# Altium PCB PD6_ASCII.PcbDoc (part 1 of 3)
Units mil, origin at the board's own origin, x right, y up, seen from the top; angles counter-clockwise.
Board outline 8543.31 x 5314.96 mil, 4 copper layers (Top Layer, VBAT Plane, GND Plane, Bottom Layer), stack 62.8 mil thick; 258 components, 142 nets, 690 pads, 87 vias.
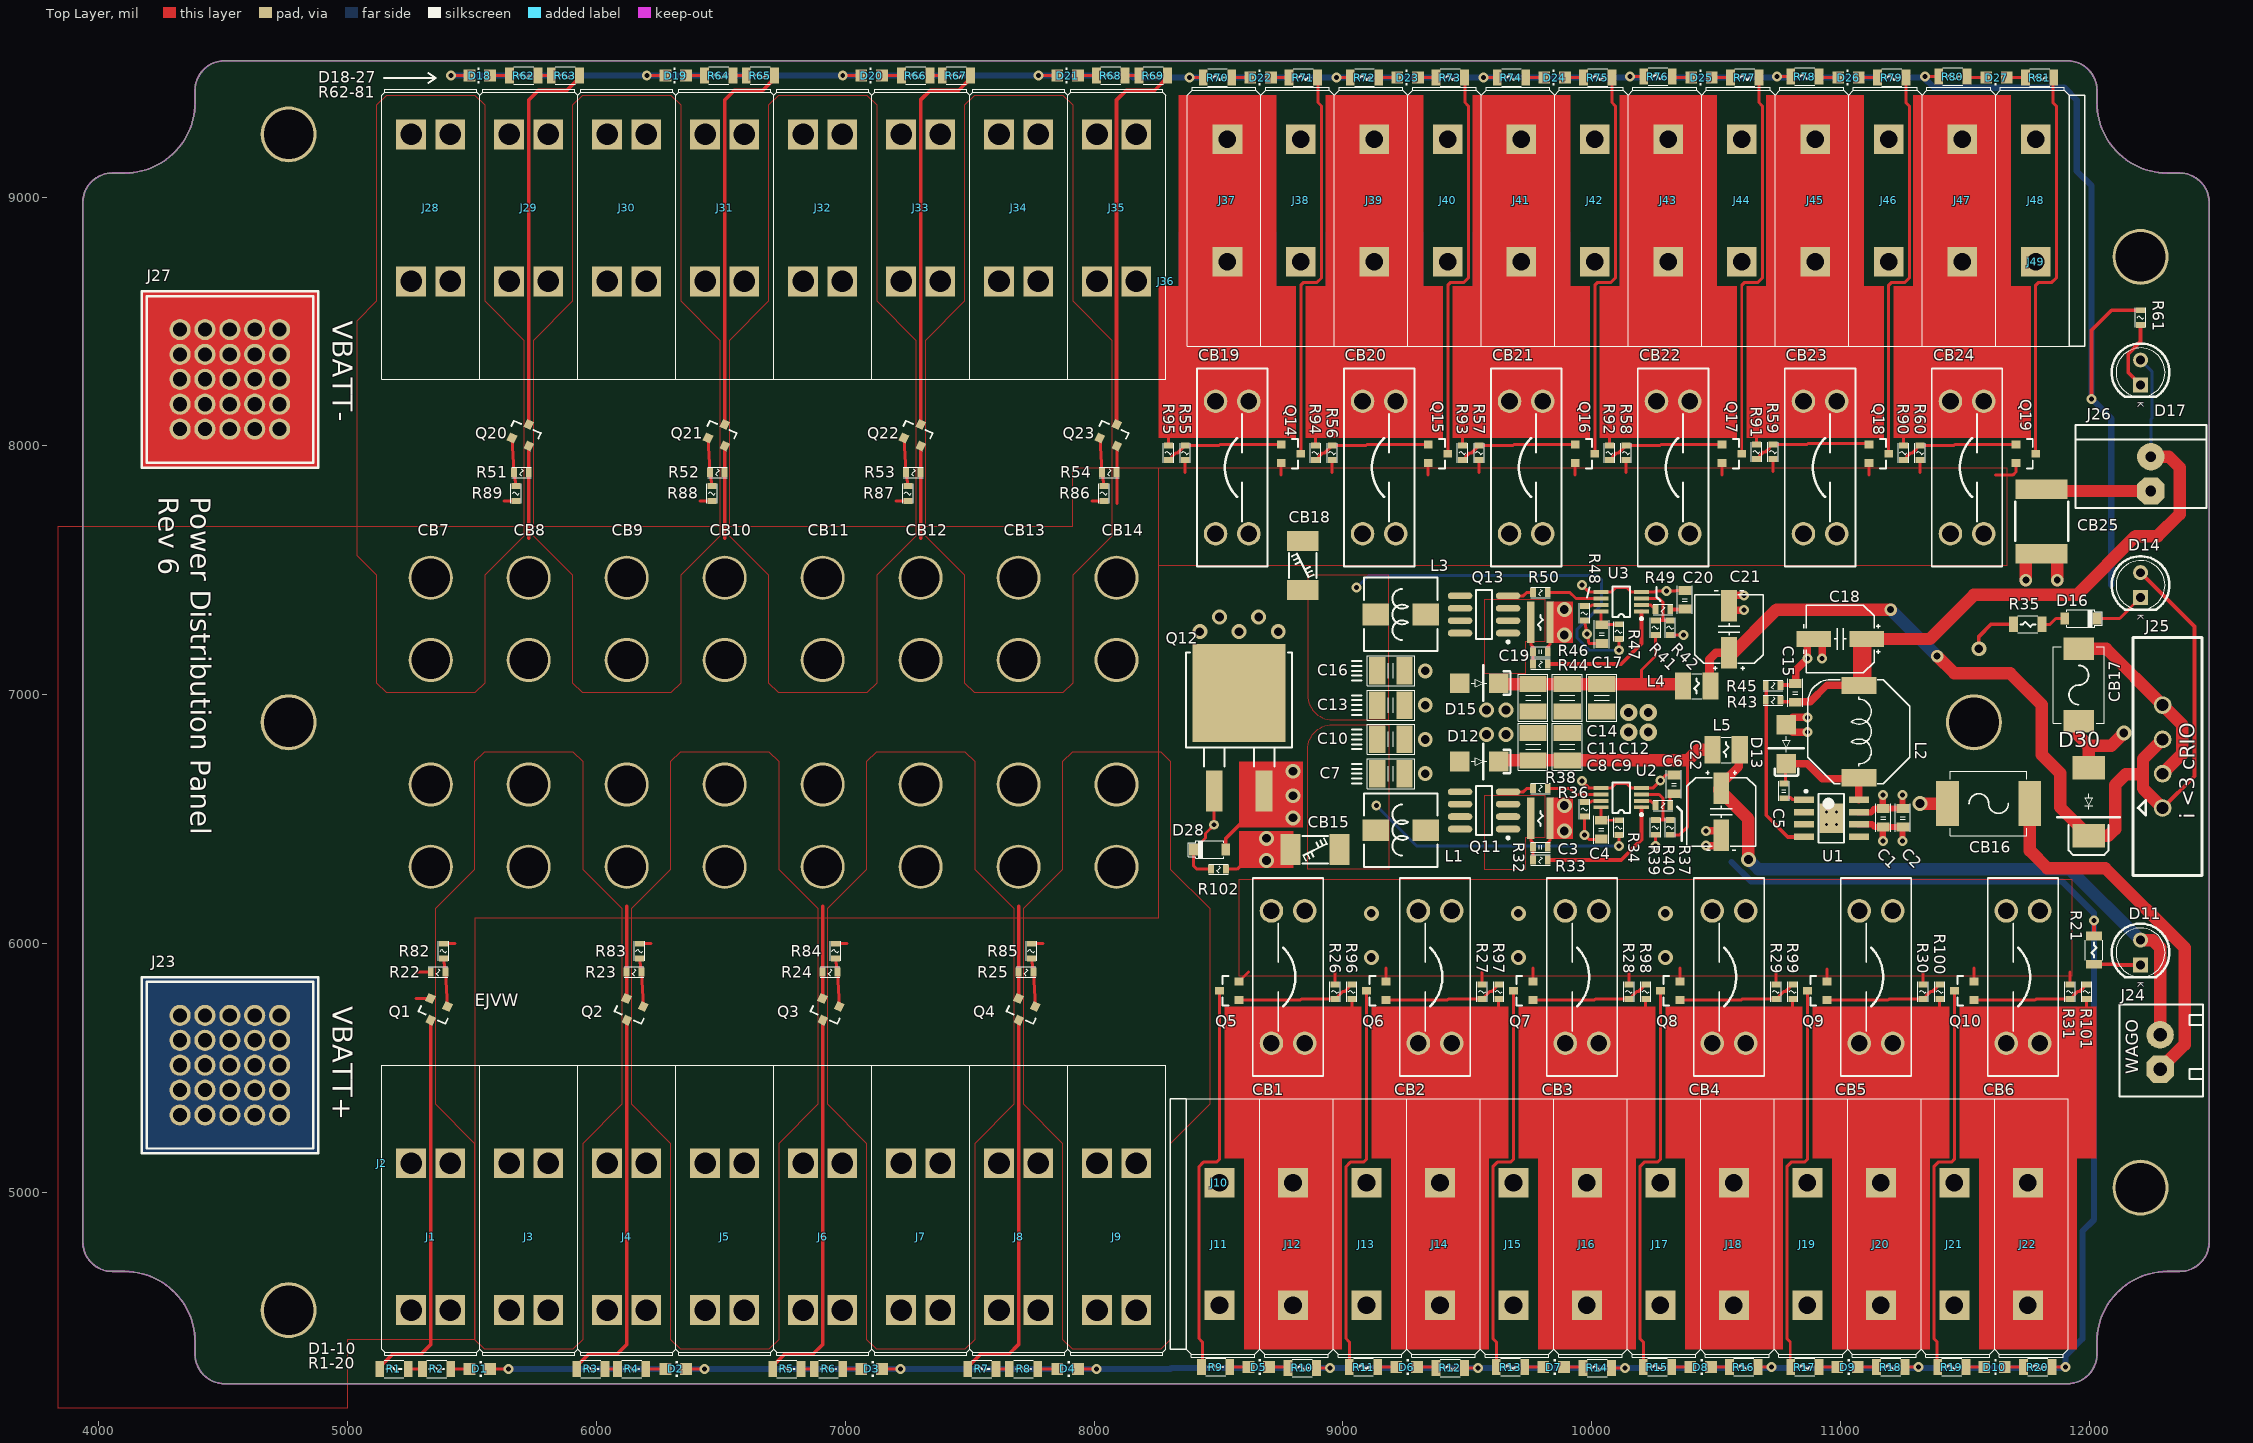
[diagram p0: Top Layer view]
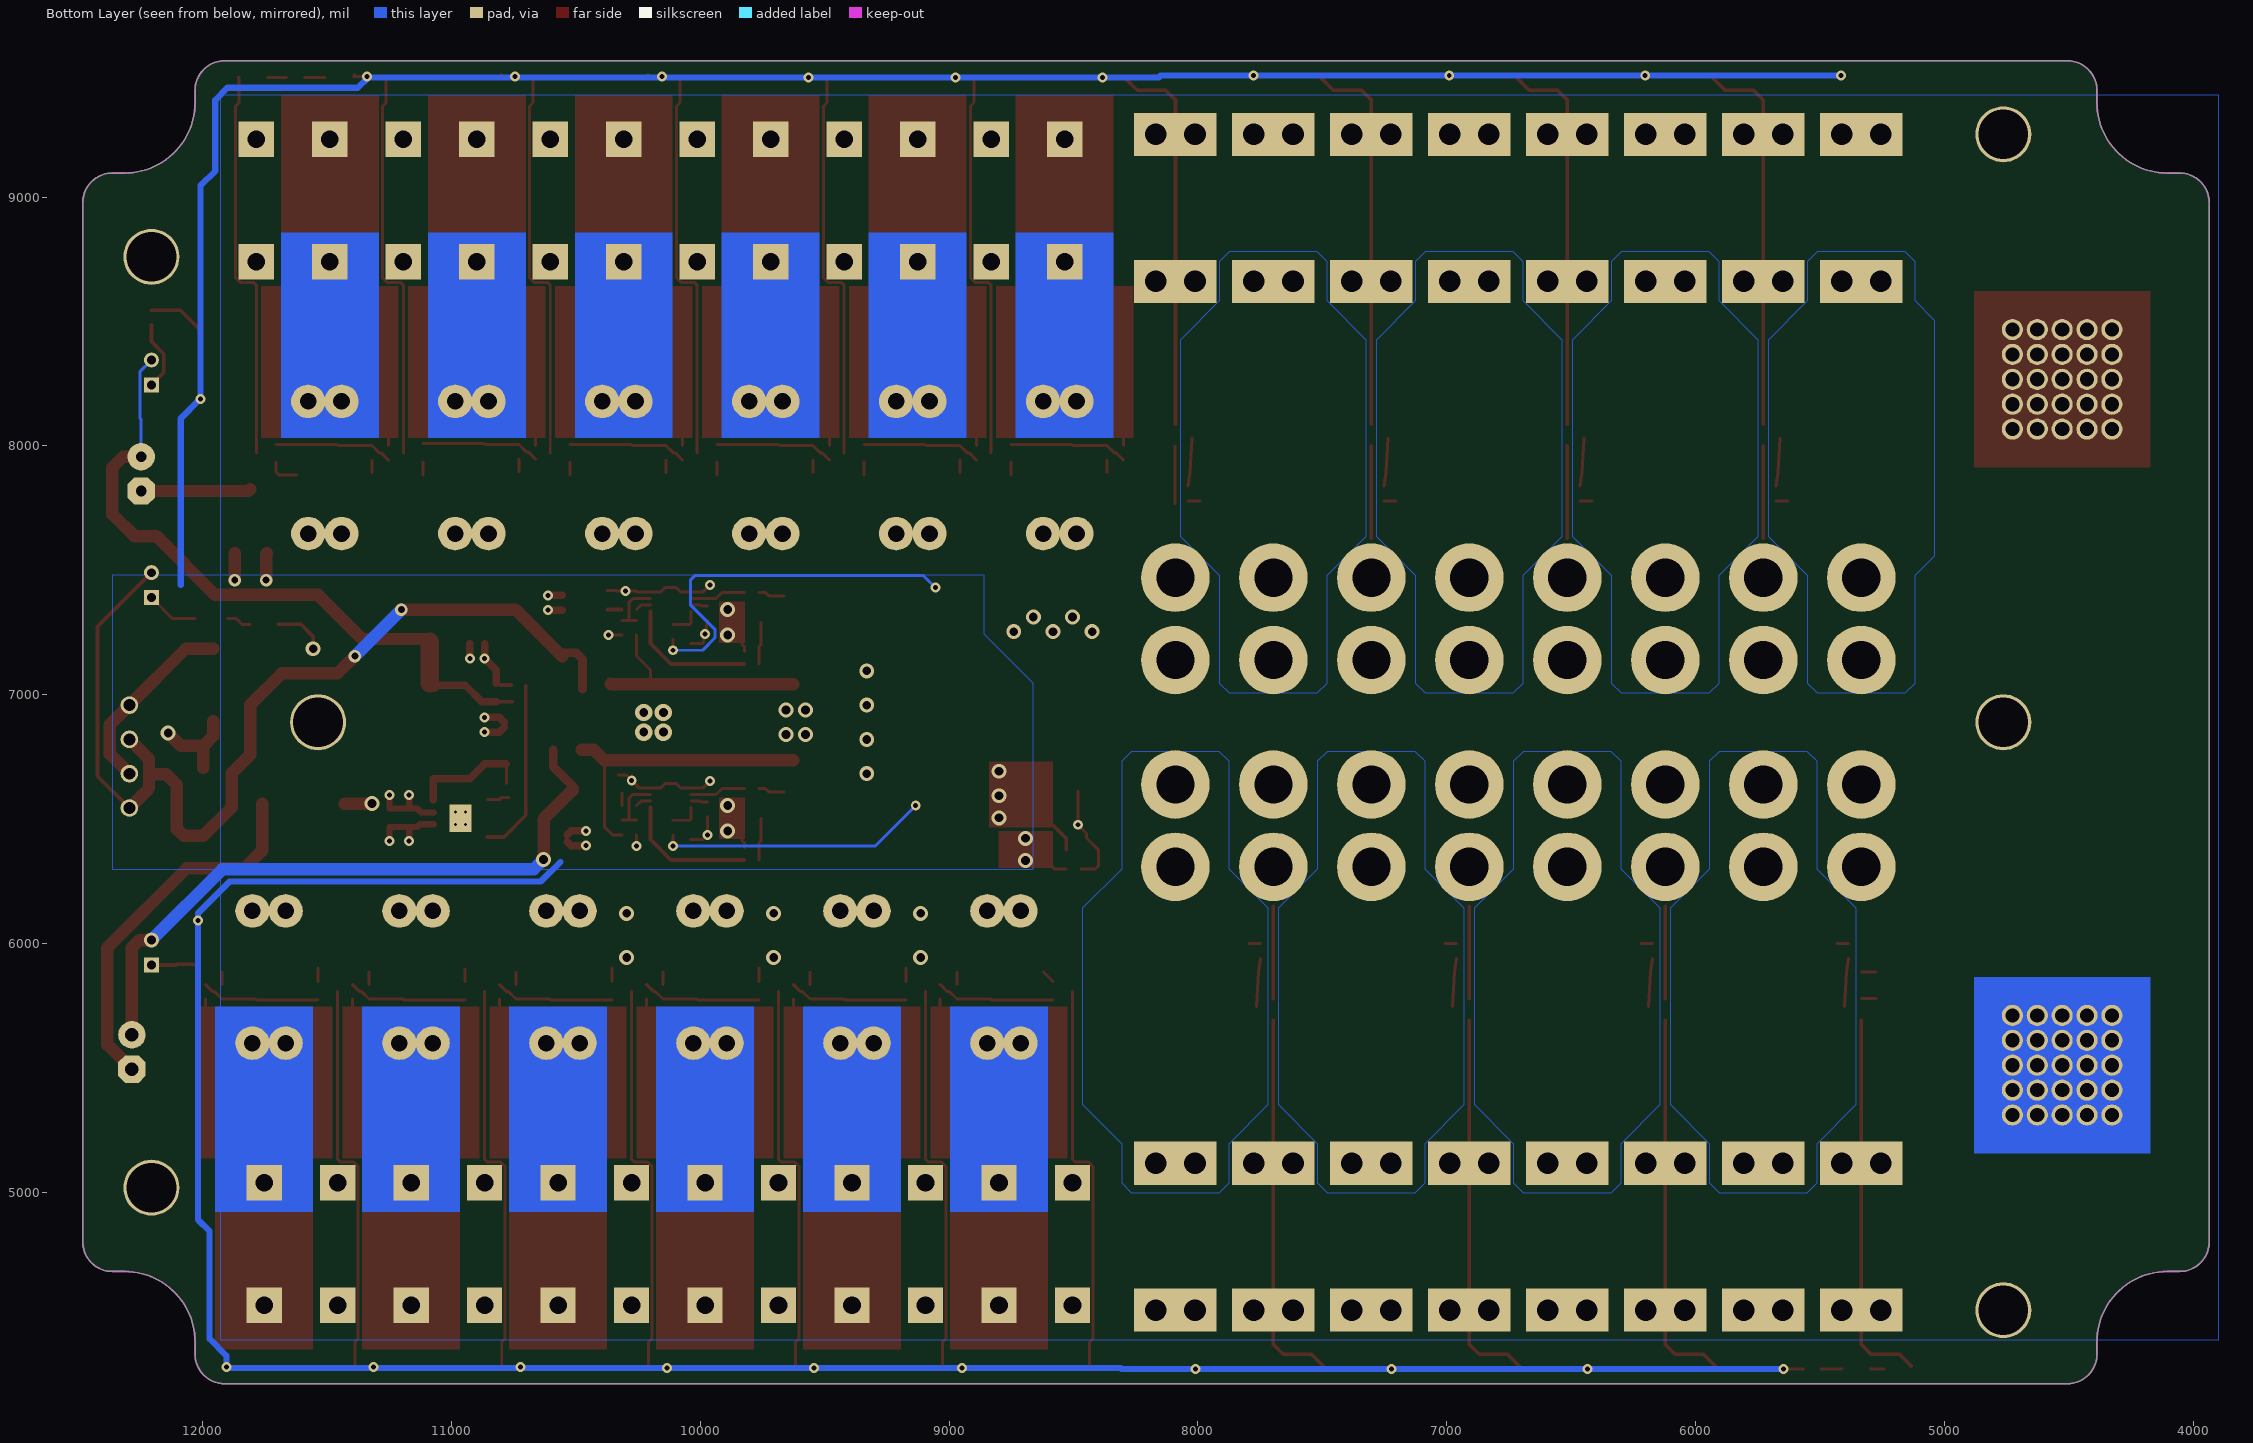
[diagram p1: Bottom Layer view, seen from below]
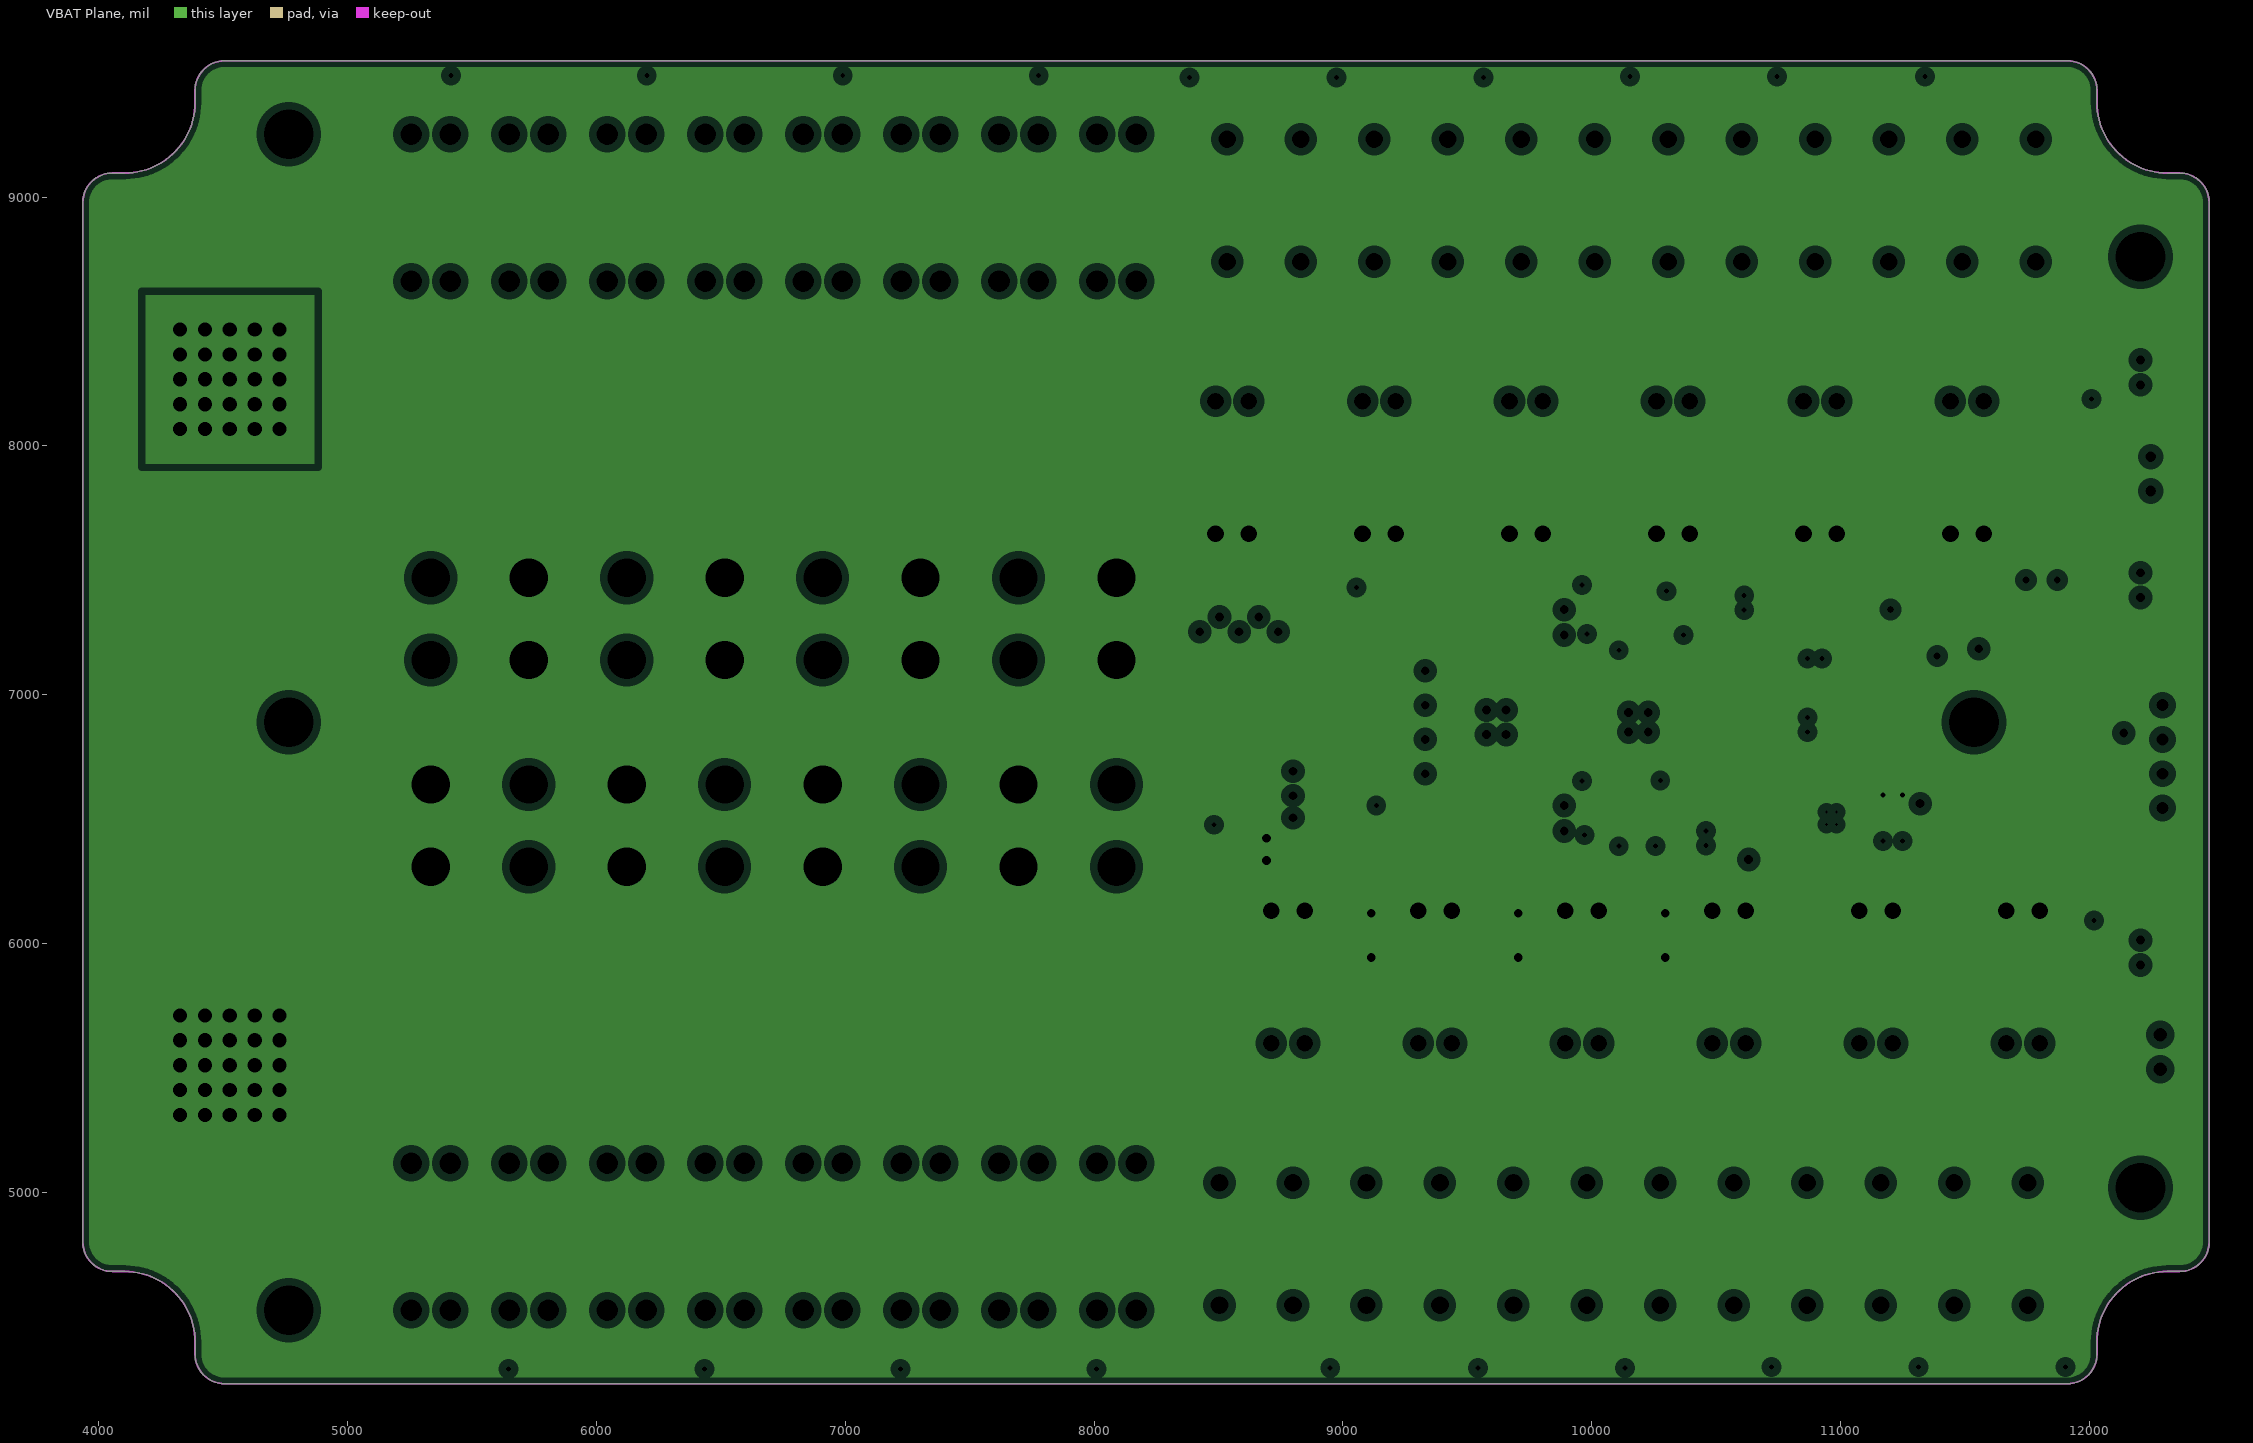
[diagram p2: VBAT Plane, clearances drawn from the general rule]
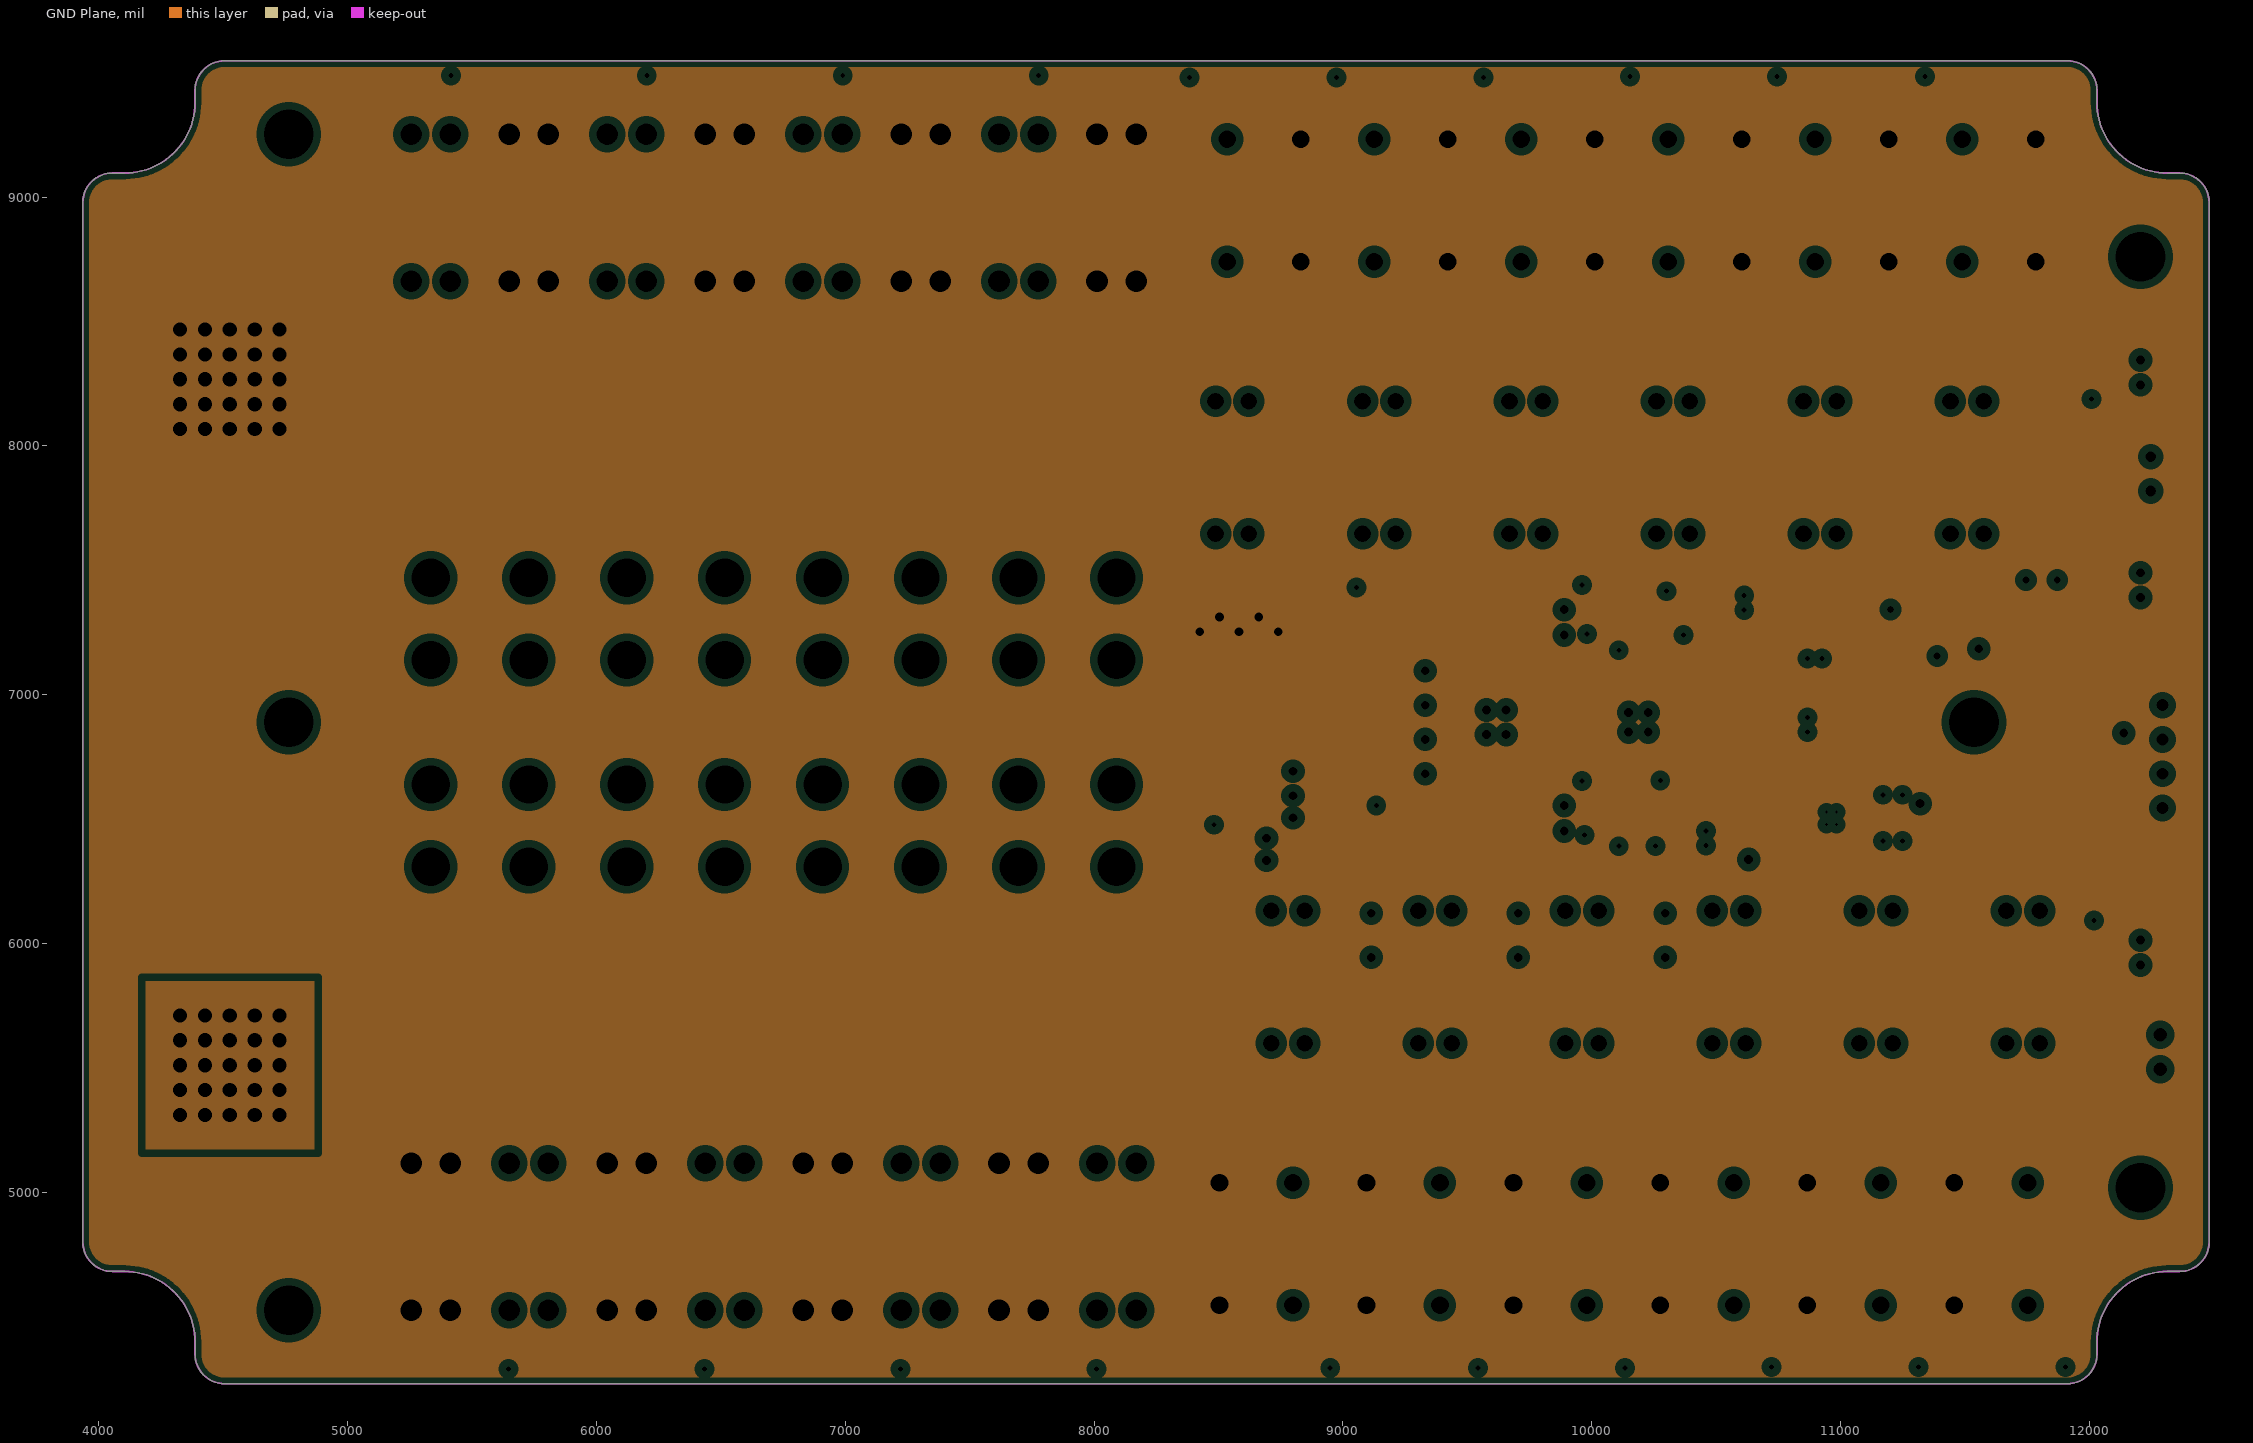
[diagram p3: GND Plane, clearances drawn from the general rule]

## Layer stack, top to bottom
Top Layer: signal copper 2.4
Dielectric: prepreg 10, FR-4, Dk 4.8
VBAT Plane: plane copper 5, net (Multiple Nets)
Dielectric: core 28, FR-4, Dk 4.8
GND Plane: plane copper 5, net (Multiple Nets)
Dielectric: prepreg 10, FR-4, Dk 4.8
Bottom Layer: signal copper 2.4

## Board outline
4055.12,4683.07 4104.33,4683.07 cw(c4104.33,4399.61) 4387.8,4399.61 4387.8,4350.39 ccw(c4505.91,4350.39) 4505.91,4232.28 11911.42,4232.28 ccw(c11911.42,4350.39) 12029.53,4350.39 12029.53,4399.61 cw(c12312.99,4399.61) 12312.99,4683.07 12362.2,4683.07 ccw(c12362.2,4801.18) 12480.31,4801.18 12480.31,8978.35 ccw(c12362.2,8978.35) 12362.2,9096.46 12312.99,9096.46 cw(c12312.99,9379.92) 12029.53,9379.92 12029.53,9429.13 ccw(c11911.42,9429.13) 11911.42,9547.24 4505.91,9547.24 ccw(c4505.91,9429.13) 4387.8,9429.13 4387.8,9379.92 cw(c4104.33,9379.92) 4104.33,9096.46 4055.12,9096.46 ccw(c4055.12,8978.35) 3937.01,8978.35 3937.01,4801.18 ccw(c4055.12,4801.18)

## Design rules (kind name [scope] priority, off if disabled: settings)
Clearance Clearance_Breakers [All] p0 off: scope1count=1 scope1_0_kind=Board scope1_0_value=Board scope2count=1 scope2_0_kind=Board scope2_0_value=Board commentlength=107 gap=18 // Protel DXP Scope 1 Expression Was: (HasFootprint('KEYSTONE 3555-2') OR HasFootprint('KEYSTONE 3557-2'))
Clearance Clearance_PolyPoly [All] p0 off: scope1count=1 scope1_0_kind=Board scope1_0_value=Board scope2count=1 scope2_0_kind=Board scope2_0_value=Board commentlength=69 gap=10 // Protel DXP Scope 2 Expression Was: (InPolygon or IsPad or IsFill)
Clearance CLR_Poly [All] p0 off: scope1count=1 scope1_0_kind=Board scope1_0_value=Board scope2count=1 scope2_0_kind=Board scope2_0_value=Board commentlength=50 gap=12 // Protel DXP Scope 1 Expression Was: (InPolygon)
Clearance CLR_Board_Edge [All] p0 off: scope1count=1 scope1_0_kind=Board scope1_0_value=Board scope2count=1 scope2_0_kind=Layer scope2_0_value=TOP commentlength=50 gap=20 // Protel DXP Scope 1 Expression Was: (InPolygon)
Clearance [All] p0: scope1count=1 scope1_0_kind=Board scope1_0_value=Board scope2count=1 scope2_0_kind=Board scope2_0_value=Board commentlength=0 gap=9.02
Clearance "CLR Inner Planes" [All] p0 off: scope1count=1 scope1_0_kind=Board scope1_0_value=Board scope2count=1 scope2_0_kind=Board scope2_0_value=Board commentlength=84 gap=30 // Protel DXP Scope 1 Expression Was: OnLayer('GND Plane') or OnLayer('VBAT Plane')
Clearance "CLR Inner Planes" [OnLayer('GND Plane') or OnLayer('VBAT Plane')] p1: gap=30
Clearance Clearance_Breakers [(HasFootprint('KEYSTONE 3555-2') OR HasFootprint('KEYSTONE 3557-2'))] p2: gap=18
Clearance CLR_Board_Edge [(InPolygon) vs OnLayer('Keep-Out Layer')] p3: gap=20
Clearance Clearance_PolyPoly [(InPolygon) vs (InPolygon or IsPad or IsFill)] p4: gap=10
Clearance CLR_Poly [(InPolygon)] p5: gap=12
Clearance [All] p6: gap=9.02
ComponentClearance "CC Wago236" [All] p0 off: scope1count=1 scope1_0_kind=Board scope1_0_value=Board scope2count=1 scope2_0_kind=Board scope2_0_value=Board commentlength=101 gap=-39.37 collisioncheckmode=3 // Protel DXP Scope 1 Expression Was: (HasFootprint('WAGO 236-74X') OR HasFootprint('WAGO 236-75X'))
ComponentClearance "ComponentClearance_WAGO Small" [All] p0 off: scope1count=1 scope1_0_kind=Board scope1_0_value=Board scope2count=1 scope2_0_kind=Board scope2_0_value=Board commentlength=137 gap=-3937.01 collisioncheckmode=3 // Protel DXP Scope 2 Expression Was: (HasFootprint('WAGO 745-83X') OR HasFootprint('WAGO 745-83X Red') OR HasFootprint('WAGO 745-300'))
ComponentClearance ComponentClearance_WAGOs [All] p0 off: scope1count=1 scope1_0_kind=Board scope1_0_value=Board scope2count=1 scope2_0_kind=Board scope2_0_value=Board commentlength=137 gap=-7874.02 collisioncheckmode=3 // Protel DXP Scope 2 Expression Was: (HasFootprint('WAGO 745-85X') OR HasFootprint('WAGO 745-85X Red') OR HasFootprint('WAGO 745-500'))
ComponentClearance [All] p0 off: scope1count=1 scope1_0_kind=Board scope1_0_value=Board scope2count=1 scope2_0_kind=Board scope2_0_value=Board commentlength=0 gap=10 collisioncheckmode=3
ComponentClearance "CC Wago236" [(HasFootprint('WAGO 236-74X') OR HasFootprint('WAGO 236-75X'))] p1 off: gap=-39.37 collisioncheckmode=3 verticalgap=0 showdistances=FALSE
ComponentClearance "ComponentClearance_WAGO Small" [(HasFootprint('WAGO 745-83X') OR HasFootprint('WAGO 745-83X Red') OR HasFootprint('WAGO 745-300')) vs (HasFootprint('WAGO 745-83X') OR HasFootprint('WAGO 745-83X Red') OR HasFootprint('WAGO 745-300'))] p2 off: gap=-3937.01 collisioncheckmode=3 verticalgap=0 showdistances=FALSE
ComponentClearance ComponentClearance_WAGOs [(HasFootprint('WAGO 745-85X') OR HasFootprint('WAGO 745-85X Red') OR HasFootprint('WAGO 745-500')) vs (HasFootprint('WAGO 745-85X') OR HasFootprint('WAGO 745-85X Red') OR HasFootprint('WAGO 745-500'))] p3 off: gap=-7874.02 collisioncheckmode=3 verticalgap=0 showdistances=FALSE
ComponentClearance [All] p4 off: gap=10 collisioncheckmode=3 verticalgap=10 showdistances=FALSE
DiffPairsRouting [All] p0: scope1count=1 scope1_0_kind=Board scope1_0_value=Board scope2count=1 scope2_0_kind=Board scope2_0_value=Board commentlength=0
FanoutControl Fanout_Default [All] p0: scope1count=1 scope1_0_kind=Board scope1_0_value=Board scope2count=1 scope2_0_kind=Board scope2_0_value=Board commentlength=30 // Fanout_Default (Default Rule)
FanoutControl Fanout_Small [All] p0 off: scope1count=1 scope1_0_kind=Board scope1_0_value=Board scope2count=1 scope2_0_kind=Board scope2_0_value=Board commentlength=84 // Protel DXP Scope 1 Expression Was: (CompPinCount < 5)   Fanout_Small (Default Rule)
FanoutControl Fanout_SOIC [All] p0 off: scope1count=1 scope1_0_kind=Board scope1_0_value=Board scope2count=1 scope2_0_kind=Board scope2_0_value=Board commentlength=71 // Protel DXP Scope 1 Expression Was: IsSOIC   Fanout_SOIC (Default Rule)
FanoutControl Fanout_LCC [All] p0 off: scope1count=1 scope1_0_kind=Board scope1_0_value=Board scope2count=1 scope2_0_kind=Board scope2_0_value=Board commentlength=69 // Protel DXP Scope 1 Expression Was: IsLCC   Fanout_LCC (Default Rule)
FanoutControl Fanout_BGA [All] p0 off: scope1count=1 scope1_0_kind=Board scope1_0_value=Board scope2count=1 scope2_0_kind=Board scope2_0_value=Board commentlength=69 // Protel DXP Scope 1 Expression Was: IsBGA   Fanout_BGA (Default Rule)
Height Height_Bottom [All] p0: scope1count=1 scope1_0_kind=Layer scope1_0_value=BOTTOM scope2count=1 scope2_0_kind=Board scope2_0_value=Board commentlength=0
Height [All] p0: scope1count=1 scope1_0_kind=Board scope1_0_value=Board scope2count=1 scope2_0_kind=Board scope2_0_value=Board commentlength=0
Height Height_Bottom [OnLayer('Bottom Layer')] p1: minheight=0 maxheight=137.8 prefheight=39.37
Height [All] p2: minheight=0 maxheight=2500 prefheight=500
HoleSize [All] p0: scope1count=1 scope1_0_kind=Board scope1_0_value=Board scope2count=1 scope2_0_kind=Board scope2_0_value=Board commentlength=0 absolutevalues=TRUE maxlimit=500 minlimit=10 maxpercent=80.000 minpercent=20.000
HoleSize [All] p1: absolutevalues=TRUE maxlimit=500 minlimit=10 maxpercent=80.000 minpercent=20.000
LayerPairs [All] p0: scope1count=1 scope1_0_kind=Board scope1_0_value=Board scope2count=1 scope2_0_kind=Board scope2_0_value=Board commentlength=0 enforce=TRUE
MinimumAnnularRing [All] p0: scope1count=1 scope1_0_kind=Board scope1_0_value=Board scope2count=1 scope2_0_kind=Board scope2_0_value=Board commentlength=0 minimumring=10
MinimumAnnularRing [All] p1: minimumring=10
PasteMaskExpansion [All] p0: scope1count=1 scope1_0_kind=Board scope1_0_value=Board scope2count=1 scope2_0_kind=Board scope2_0_value=Board commentlength=0 expansion=0
PlaneClearance [All] p0: scope1count=1 scope1_0_kind=Board scope1_0_value=Board scope2count=1 scope2_0_kind=Board scope2_0_value=Board commentlength=0 clearance=30
PlaneClearance [All] p1: clearance=30
PlaneConnect PC_Wurth [All] p0 off: scope1count=1 scope1_0_kind=Board scope1_0_value=Board scope2count=1 scope2_0_kind=Board scope2_0_value=Board commentlength=70 planeconnectstyle=Direct reliefexpansion=20 reliefentries=4 reliefconductorwidth=10 reliefairgap=10 // Protel DXP Scope 1 Expression Was: (HasFootprint('WURTH 7460719'))
PlaneConnect PC_Honkin [All] p0 off: scope1count=1 scope1_0_kind=Board scope1_0_value=Board scope2count=1 scope2_0_kind=Board scope2_0_value=Board commentlength=79 planeconnectstyle=Direct reliefexpansion=20 reliefentries=2 reliefconductorwidth=10 reliefairgap=10 // Protel DXP Scope 1 Expression Was: (InComponent('J1') OR InComponent('J2'))
PlaneConnect PC_Vias [All] p0 off: scope1count=1 scope1_0_kind=Board scope1_0_value=Board scope2count=1 scope2_0_kind=Board scope2_0_value=Board commentlength=44 planeconnectstyle=Direct reliefexpansion=20 reliefentries=4 reliefconductorwidth=10 reliefairgap=10 // Protel DXP Scope 1 Expression Was: IsVia
PlaneConnect [All] p0: scope1count=1 scope1_0_kind=Board scope1_0_value=Board scope2count=1 scope2_0_kind=Board scope2_0_value=Board commentlength=0 planeconnectstyle=Direct reliefexpansion=30 reliefentries=4 reliefconductorwidth=30 reliefairgap=20
PlaneConnect PC_Breakers [All] p0 off: scope1count=1 scope1_0_kind=Board scope1_0_value=Board scope2count=1 scope2_0_kind=Board scope2_0_value=Board commentlength=107 planeconnectstyle=Direct reliefexpansion=20 reliefentries=4 reliefconductorwidth=60 reliefairgap=20 // Protel DXP Scope 1 Expression Was: (HasFootprint('KEYSTONE 3555-2') OR HasFootprint('KEYSTONE 3557-2'))
PlaneConnect "PC Wagos" [All] p0 off: scope1count=1 scope1_0_kind=Board scope1_0_value=Board scope2count=1 scope2_0_kind=Board scope2_0_value=Board commentlength=101 planeconnectstyle=Direct reliefexpansion=20 reliefentries=4 reliefconductorwidth=40 reliefairgap=25 // Protel DXP Scope 1 Expression Was: (HasFootprint('WAGO 745-83X') OR HasFootprint('WAGO 745-85X'))
PlaneConnect PC_PowerSO8 [All] p0 off: scope1count=1 scope1_0_kind=Board scope1_0_value=Board scope2count=1 scope2_0_kind=Board scope2_0_value=Board commentlength=64 planeconnectstyle=Direct reliefexpansion=20 reliefentries=4 reliefconductorwidth=10 reliefairgap=10 // Protel DXP Scope 1 Expression Was: (HasFootprint('TPS543X'))
PlaneConnect PC_PowerSO8 [(HasFootprint('TPS543X'))] p1: planeconnectstyle=Direct reliefexpansion=20 reliefentries=4 reliefconductorwidth=10 reliefairgap=10
PlaneConnect PC_Wurth [(HasFootprint('WURTH 7460719'))] p2: planeconnectstyle=Direct reliefexpansion=20 reliefentries=4 reliefconductorwidth=10 reliefairgap=10
PlaneConnect "PC Wagos" [(HasFootprint('WAGO 745-83X') OR HasFootprint('WAGO 745-85X'))] p3: planeconnectstyle=Direct reliefexpansion=20 reliefentries=4 reliefconductorwidth=40 reliefairgap=25
PlaneConnect PC_Breakers [(HasFootprint('KEYSTONE 3555-2') OR HasFootprint('KEYSTONE 3557-2'))] p4: planeconnectstyle=Direct reliefexpansion=20 reliefentries=4 reliefconductorwidth=60 reliefairgap=20
PlaneConnect PC_Honkin [(InComponent('J1') OR InComponent('J2'))] p5: planeconnectstyle=Direct reliefexpansion=20 reliefentries=2 reliefconductorwidth=10 reliefairgap=10
PlaneConnect PC_Vias [IsVia] p6: planeconnectstyle=Direct reliefexpansion=20 reliefentries=4 reliefconductorwidth=10 reliefairgap=10
PlaneConnect [All] p7: planeconnectstyle=Direct reliefexpansion=30 reliefentries=4 reliefconductorwidth=30 reliefairgap=20
PolygonConnect PGC_Breakers [All] p0 off: scope1count=1 scope1_0_kind=Board scope1_0_value=Board scope2count=1 scope2_0_kind=Board scope2_0_value=Board commentlength=105 connectstyle=Direct reliefconductorwidth=50 reliefentries=4 polygonreliefangle="45 Angle" // Protel DXP Scope 1 Expression Was: HasFootprint('KEYSTONE 3555-2') OR HasFootprint('KEYSTONE 3557-2')
PolygonConnect PGC_Vias [All] p0 off: scope1count=1 scope1_0_kind=Board scope1_0_value=Board scope2count=1 scope2_0_kind=Board scope2_0_value=Board commentlength=46 connectstyle=Direct reliefconductorwidth=10 reliefentries=4 polygonreliefangle="90 Angle" // Protel DXP Scope 1 Expression Was: (IsVia)
PolygonConnect PGC_VBAT_HP [All] p0 off: scope1count=1 scope1_0_kind=Board scope1_0_value=Board scope2count=1 scope2_0_kind=Board scope2_0_value=Board commentlength=115 connectstyle=Direct reliefconductorwidth=10 reliefentries=4 polygonreliefangle="45 Angle" // Protel DXP Scope 2 Expression Was: IsNamedPolygon('Top Layer-VBAT HP') or IsNamedPolygon('Bottom Layer-GND HP')
PolygonConnect [All] p0: scope1count=1 scope1_0_kind=Board scope1_0_value=Board scope2count=1 scope2_0_kind=Board scope2_0_value=Board commentlength=0 connectstyle=Direct reliefconductorwidth=10 reliefentries=4 polygonreliefangle="90 Angle"
PolygonConnect "PGC Wago" [All] p0 off: scope1count=1 scope1_0_kind=Board scope1_0_value=Board scope2count=1 scope2_0_kind=Board scope2_0_value=Board commentlength=101 connectstyle=Direct reliefconductorwidth=45 reliefentries=4 polygonreliefangle="90 Angle" // Protel DXP Scope 1 Expression Was: (HasFootprint('WAGO 745-83X') OR HasFootprint('WAGO 745-85X'))
PolygonConnect "PGC Wago" [(HasFootprint('WAGO 745-83X') OR HasFootprint('WAGO 745-85X'))] p1: connectstyle=Direct reliefconductorwidth=45 reliefentries=4 polygonreliefangle="90 Angle"
PolygonConnect PGC_Breakers [HasFootprint('KEYSTONE 3555-2') OR HasFootprint('KEYSTONE 3557-2')] p2: connectstyle=Direct reliefconductorwidth=50 reliefentries=4 polygonreliefangle="45 Angle"
PolygonConnect PGC_Vias [(IsVia)] p3: connectstyle=Direct reliefconductorwidth=10 reliefentries=4 polygonreliefangle="90 Angle"
PolygonConnect PGC_VBAT_HP [All vs IsNamedPolygon('Top Layer-VBAT HP') or IsNamedPolygon('Bottom Layer-GND HP')] p4: connectstyle=Direct reliefconductorwidth=10 reliefentries=4 polygonreliefangle="45 Angle"
PolygonConnect [All] p5: connectstyle=Direct reliefconductorwidth=10 reliefentries=4 polygonreliefangle="90 Angle"
RoomDefinition U1000 [All] p0: scope1count=1 scope1_0_kind=ComponentClass scope1_0_value=U1000 scope2count=1 scope2_0_kind=Board scope2_0_value=Board commentlength=0 region_x1=88582677 region_y1=68897638 region_x2=108169291 region_y2=74803150 confinementstyle=ConfineIn
RoomDefinition "U_5V_3A Supply" [All] p0: scope1count=1 scope1_0_kind=ComponentClass scope1_0_value="U_5V_3A Supply" scope2count=1 scope2_0_kind=Board scope2_0_value=Board commentlength=0 region_x1=106692913 region_y1=63779528 region_x2=112992126 region_y2=73818898 confinementstyle=ConfineIn
RoomDefinition HPB2 [All] p0: scope1count=1 scope1_0_kind=ComponentClass scope1_0_value=HPB2 scope2count=1 scope2_0_kind=Board scope2_0_value=Board commentlength=0 region_x1=50393701 region_y1=61023622 region_x2=83858268 region_y2=96456693 confinementstyle=ConfineIn
RoomDefinition LPB1 [All] p0: scope1count=1 scope1_0_kind=ComponentClass scope1_0_value=LPB1 scope2count=1 scope2_0_kind=Board scope2_0_value=Board commentlength=0 region_x1=82874016 region_y1=41338583 region_x2=122244094 region_y2=68897638 confinementstyle=ConfineIn
RoomDefinition HPB1 [All] p0: scope1count=1 scope1_0_kind=ComponentClass scope1_0_value=HPB1 scope2count=1 scope2_0_kind=Board scope2_0_value=Board commentlength=0 region_x1=50393701 region_y1=41338583 region_x2=83858268 region_y2=76771654 confinementstyle=ConfineIn
RoomDefinition LPB2 [All] p0: scope1count=1 scope1_0_kind=ComponentClass scope1_0_value=LPB2 scope2count=1 scope2_0_kind=Board scope2_0_value=Board commentlength=0 region_x1=80629922 region_y1=68897638 region_x2=120000000 region_y2=96456693 confinementstyle=ConfineIn
RoomDefinition "U_12V_2A Supply" [All] p0: scope1count=1 scope1_0_kind=ComponentClass scope1_0_value="U_12V_2A Supply" scope2count=1 scope2_0_kind=Board scope2_0_value=Board commentlength=0 region_x1=88582677 region_y1=62992126 region_x2=108169291 region_y2=68897638 confinementstyle=ConfineIn
RoomDefinition "U_12V_2A Supply" [InComponentClass('U_12V_2A Supply')] p1: confinementstyle=ConfineIn formatcopy=TRUE lockcomponents=FALSE outline 8858.27,6299.21 10816.93,6299.21 10816.93,6889.76 8858.27,6889.76
RoomDefinition LPB2 [InComponentClass('LPB2')] p2: confinementstyle=ConfineIn formatcopy=TRUE lockcomponents=FALSE outline 8062.99,6889.76 12000,6889.76 12000,9645.67 8062.99,9645.67
RoomDefinition HPB1 [InComponentClass('HPB1')] p3: confinementstyle=ConfineIn formatcopy=TRUE lockcomponents=FALSE outline 8385.83,7677.17 5039.37,7677.17 5039.37,4133.86 8385.83,4133.86
RoomDefinition LPB1 [InComponentClass('LPB1')] p4: confinementstyle=ConfineIn formatcopy=TRUE lockcomponents=FALSE outline 12224.41,6889.76 8287.4,6889.76 8287.4,4133.86 12224.41,4133.86
RoomDefinition U1000 [InComponentClass('U1000')] p5: confinementstyle=ConfineIn formatcopy=TRUE lockcomponents=FALSE outline 8858.27,6889.76 10816.93,6889.76 10816.93,7480.31 8858.27,7480.31
RoomDefinition "U_5V_3A Supply" [InComponentClass('U_5V_3A Supply')] p6: confinementstyle=ConfineIn formatcopy=TRUE lockcomponents=FALSE outline 11299.21,6377.95 11299.21,7381.89 10669.29,7381.89 10669.29,6377.95
RoomDefinition HPB2 [InComponentClass('HPB2')] p7: confinementstyle=ConfineIn formatcopy=TRUE lockcomponents=FALSE outline 5039.37,6102.36 8385.83,6102.36 8385.83,9645.67 5039.37,9645.67
RoutingCorners [All] p0: scope1count=1 scope1_0_kind=Board scope1_0_value=Board scope2count=1 scope2_0_kind=Board scope2_0_value=Board commentlength=0 cornerstyle=45-Degree minsetback=100 maxsetback=100
RoutingLayers [All] p0: scope1count=1 scope1_0_kind=Board scope1_0_value=Board scope2count=1 scope2_0_kind=Board scope2_0_value=Board commentlength=0 top layer=Automatic bottom layer=Automatic
RoutingPriority [All] p0: scope1count=1 scope1_0_kind=Board scope1_0_value=Board scope2count=1 scope2_0_kind=Board scope2_0_value=Board commentlength=0
RoutingTopology [All] p0: scope1count=1 scope1_0_kind=Board scope1_0_value=Board scope2count=1 scope2_0_kind=Board scope2_0_value=Board commentlength=0 topology=Shortest
RoutingVias [All] p0: scope1count=1 scope1_0_kind=Board scope1_0_value=Board scope2count=1 scope2_0_kind=Board scope2_0_value=Board commentlength=0 holewidth=30 width=50 viastyle="Through Hole" minholewidth=10 minwidth=30 maxholewidth=225 maxwidth=250
RoutingVias [All] p1: holewidth=30 width=50 viastyle="Through Hole" minholewidth=10 minwidth=30 maxholewidth=225 maxwidth=250
ShortCircuit [All] p0: scope1count=1 scope1_0_kind=Board scope1_0_value=Board scope2count=1 scope2_0_kind=Board scope2_0_value=Board commentlength=0 allowed=FALSE
SolderMaskExpansion [All] p0: scope1count=1 scope1_0_kind=Board scope1_0_value=Board scope2count=1 scope2_0_kind=Board scope2_0_value=Board commentlength=0 expansion=4
SolderMaskExpansion [All] p1: expansion=4
TestPointUsage [All] p0: scope1count=1 scope1_0_kind=Board scope1_0_value=Board scope2count=1 scope2_0_kind=Board scope2_0_value=Board commentlength=0 valid=0 allowmultiple=FALSE
TestPointUsage [All] p1: valid=0 allowmultiple=FALSE
Testpoint [All] p0: scope1count=1 scope1_0_kind=Board scope1_0_value=Board scope2count=1 scope2_0_kind=Board scope2_0_value=Board commentlength=0 side=15 testpointundercomponent=TRUE minsize=40 maxsize=100 preferedsize=60 minholesize=0 maxholesize=40 preferedholesize=32 testpointgrid=1 style=1021 order=0-112345678
Testpoint [All] p1: side=15 testpointundercomponent=TRUE minsize=40 maxsize=100 preferedsize=60 minholesize=0 maxholesize=40 preferedholesize=32 testpointgrid=1 style=1021 order=0-112345678
UnRoutedNet [All] p0: scope1count=1 scope1_0_kind=Board scope1_0_value=Board scope2count=1 scope2_0_kind=Board scope2_0_value=Board commentlength=0
Width [All] p0: scope1count=1 scope1_0_kind=Board scope1_0_value=Board scope2count=1 scope2_0_kind=Board scope2_0_value=Board commentlength=0 maxlimit=500 minlimit=10 preferedwidth=12
Width Width_InnerPlanes [All] p0 off: scope1count=1 scope1_0_kind=Board scope1_0_value=Board scope2count=1 scope2_0_kind=Board scope2_0_value=Board commentlength=84 maxlimit=100 minlimit=25 preferedwidth=30 // Protel DXP Scope 1 Expression Was: OnLayer('GND Plane') or OnLayer('VBAT Plane')
Width Width_InnerPlanes [OnLayer('GND Plane') or OnLayer('VBAT Plane')] p1: maxlimit=100 minlimit=25 preferedwidth=30
Width [All] p2: maxlimit=500 minlimit=10 preferedwidth=12
14 further rules are at their usual default settings.

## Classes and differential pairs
component class "U_12V_2A Supply": C3 C4 C6 C7 C8 C9 C10 C22 D12 L1 L5 Q11 R32 R33 R34 R36 R37 R38 R39 R40 U2
component class "U_5V_3A Supply": C1 C2 C5 C15 C18 D13 L2 R43 R45 U1
component class PS1: CB15 CB16 CB17 CB18 CB25 D11 D14 D16 D17 D28 D30 J23 J24 J25 J26 J27 Q12 R21 R35 R61 R102
component class LPB2: CB19 CB20 CB21 CB22 CB23 CB24 D22 D23 D24 D25 D26 D27 J37 J38 J39 J40 J41 J42 J43 J44 J45 J46 J47 J48 J49 Q14 Q15 Q16 Q17 Q18 Q19 R55 R56 R57 R58 R59 R60 R70 R71 R72 R73 R74 R75 R76 R77 R78 R79 R80 R81 R90 R91 R92 R93 R94 R95
component class LPB1: CB1 CB2 CB3 CB4 CB5 CB6 D5 D6 D7 D8 D9 D10 J10 J11 J12 J13 J14 J15 J16 J17 J18 J19 J20 J21 J22 J50 Q5 Q6 Q7 Q8 Q9 Q10 R9 R10 R11 R12 R13 R14 R15 R16 R17 R18 R19 R20 R26 R27 R28 R29 R30 R31 R96 R97 R98 R99 R100 R101
component class HPB1: CB8 CB10 CB12 CB14 D1 D2 D3 D4 J1 J2 J3 J4 J5 J6 J7 J8 J9 Q1 Q2 Q3 Q4 R1 R2 R3 R4 R5 R6 R7 R8 R22 R23 R24 R25 R82 R83 R84 R85
channel class "PD - Low Power Bank": LPB1 LPB2
channel class "PD - High Power Bank": HPB1 HPB2
component class HPB2: CB7 CB9 CB11 CB13 D18 D19 D20 D21 J28 J29 J30 J31 J32 J33 J34 J35 J36 Q20 Q21 Q22 Q23 R51 R52 R53 R54 R62 R63 R64 R65 R66 R67 R68 R69 R86 R87 R88 R89
component class U1000: C11 C12 C13 C14 C16 C17 C19 C20 C21 D15 L3 L4 Q13 R41 R42 R44 R46 R47 R48 R49 R50 U3

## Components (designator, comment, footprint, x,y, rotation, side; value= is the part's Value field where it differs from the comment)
C1 "4.7UF 0805 25V X5R" C0805_C 11171.26,6505.91 r90 top (schematic designator C8)
C2 "4.7UF 0805 25V X5R" C0805_C 11250,6505.91 r90 top (schematic designator C9)
C3 "0.01uF 0603" C0603_C 9793.31,6387.8 r180 top (schematic designator C15)
C4 "0.1uF 0805 Bypass" C0805_C 10037.4,6458.66 r90 top (schematic designator C13)
C5 "0.01uF 0603" C0603_C 10771.65,6614.17 r90 top (schematic designator C10)
C6 "0.1uF 0805 Bypass" C0805_C 10330,6640 r270 top (schematic designator C14)
C7 "22uF 1210 High I_RMS" C1210_C 9192.91,6683.07 r180 top (schematic designator C16)
C8 "22uF 1210 High I_RMS" C1210_C 9763.78,6791.34 r270 top (schematic designator C18)
C9 "22uF 1210 High I_RMS" C1210_C 9901.57,6791.34 r270 top (schematic designator C17)
C10 "22uF 1210 High I_RMS" C1210_C 9192.91,6820.87 r180 top (schematic designator C19)
C11 "4.7uF 1210 High I_RMS" C1210_C 9901.57,6988.19 r90 top (schematic designator C6)
C12 "4.7uF 1210 High I_RMS" C1210_C 10039.37,6988.19 r90 top (schematic designator C5)
C13 "22uF 1210 High I_RMS" C1210_C 9192.91,6958.66 r180 top (schematic designator C4)
C14 "4.7uF 1210 High I_RMS" C1210_C 9763.78,6988.19 r90 top (schematic designator C7)
C15 "0.1uF 0805 Bypass" C0805_C 10816.93,7007.87 r270 top (schematic designator C11)
C16 "22uF 1210 High I_RMS" C1210_C 9192.91,7096.46 r180 top (schematic designator C20)
C17 "0.1uF 0805 Bypass" C0805_C 10039.37,7244.09 r90 top (schematic designator C1)
C18 "330µF SMT - Chemi-Con" "SMT-CAN NIPPON F80" 10998.03,7224.41 r270 top (schematic designator C12)
C19 "0.01uF 0603" C0603_C 9793.31,7173.23 r180 top (schematic designator C3)
C20 "0.1uF 0805 Bypass" C0805_C 10374.02,7381.89 r270 top (schematic designator C2)
C21 "100µF SMT - Panasonic" "SMT-CAN Panasonic D8" 10551.18,7263.78 r180 top
C22 "100µF SMT - Panasonic" "SMT-CAN Panasonic D8" 10520,6530 r0 top
CB1 "20/30 A Breaker Clip" "KEYSTONE 3557-2" 8779.53,5866.14 r270 top (schematic designator CB6)
CB2 "20/30 A Breaker Clip" "KEYSTONE 3557-2" 9370.08,5866.14 r270 top (schematic designator CB7)
CB3 "20/30 A Breaker Clip" "KEYSTONE 3557-2" 9960.63,5866.14 r270 top (schematic designator CB8)
CB4 "20/30 A Breaker Clip" "KEYSTONE 3557-2" 10551.18,5866.14 r270 top (schematic designator CB9)
CB5 "20/30 A Breaker Clip" "KEYSTONE 3557-2" 11141.73,5866.14 r270 top (schematic designator CB10)
CB6 "20/30 A Breaker Clip" "KEYSTONE 3557-2" 11732.28,5866.14 r270 top (schematic designator CB11)
CB7 "40 A Breaker Clip" "KEYSTONE 3555-2" 5334.65,6889.76 r90 top (schematic designator CB5)
CB8 "40 A Breaker Clip" "KEYSTONE 3555-2" 5728.35,6889.76 r270 top (schematic designator CB2)
CB9 "40 A Breaker Clip" "KEYSTONE 3555-2" 6122.05,6889.76 r90 top (schematic designator CB4)
CB10 "40 A Breaker Clip" "KEYSTONE 3555-2" 6515.75,6889.76 r270 top (schematic designator CB3)
CB11 "40 A Breaker Clip" "KEYSTONE 3555-2" 6909.45,6889.76 r90 top (schematic designator CB3)
CB12 "40 A Breaker Clip" "KEYSTONE 3555-2" 7303.15,6889.76 r270 top (schematic designator CB4)
CB13 "40 A Breaker Clip" "KEYSTONE 3555-2" 7696.85,6889.76 r90 top (schematic designator CB2)
CB14 "40 A Breaker Clip" "KEYSTONE 3555-2" 8090.55,6889.76 r270 top (schematic designator CB5)
CB15 "15A 125V" "FUSE2410 - BEL" 8887.8,6377.95 r180 top (schematic designator CB14)
CB16 "2 A Hold, 4 A Trip" PTC-MF-SM-Large 11594.49,6562.99 r0 top (schematic designator CB13)
CB17 "1.1 A Hold, 2.2 A Trip" PTC-MF-SM-Small 11956.69,7039.37 r90 top (schematic designator CB12)
CB18 "15A 125V" "FUSE2410 - BEL" 8838.58,7519.69 r90 top (schematic designator CB1)
CB19 "20/30 A Breaker Clip" "KEYSTONE 3557-2" 8555.12,7913.39 r90 top (schematic designator CB11)
CB20 "20/30 A Breaker Clip" "KEYSTONE 3557-2" 9145.67,7913.39 r90 top (schematic designator CB10)
CB21 "20/30 A Breaker Clip" "KEYSTONE 3557-2" 9736.22,7913.39 r90 top (schematic designator CB9)
CB22 "20/30 A Breaker Clip" "KEYSTONE 3557-2" 10326.77,7913.39 r90 top (schematic designator CB8)
CB23 "20/30 A Breaker Clip" "KEYSTONE 3557-2" 10917.32,7913.39 r90 top (schematic designator CB7)
CB24 "20/30 A Breaker Clip" "KEYSTONE 3557-2" 11507.87,7913.39 r90 top (schematic designator CB6)
CB25 "3 A Hold, 5 A Trip" 2920L 11807.09,7696.85 r90 top (schematic designator CB15)
D1 "Red 0805 2.0V 20mA 104mCd" "LED_0805 0.8 Red" 5531.5,4291.34 r0 top (schematic designator D2)
D2 "Red 0805 2.0V 20mA 104mCd" "LED_0805 0.8 Red" 6318.9,4291.34 r0 top (schematic designator D3)
D3 "Red 0805 2.0V 20mA 104mCd" "LED_0805 0.8 Red" 7106.3,4291.34 r0 top (schematic designator D4)
D4 "Red 0805 2.0V 20mA 104mCd" "LED_0805 0.8 Red" 7893.7,4291.34 r0 top (schematic designator D5)
D5 "Red 0805 2.0V 20mA 104mCd" "LED_0805 0.8 Red" 8661.42,4299.21 r0 top (schematic designator D6)
D6 "Red 0805 2.0V 20mA 104mCd" "LED_0805 0.8 Red" 9255.91,4299.21 r0 top (schematic designator D7)
D7 "Red 0805 2.0V 20mA 104mCd" "LED_0805 0.8 Red" 9846.46,4299.21 r0 top (schematic designator D8)
D8 "Red 0805 2.0V 20mA 104mCd" "LED_0805 0.8 Red" 10437.01,4299.21 r0 top (schematic designator D9)
D9 "Red 0805 2.0V 20mA 104mCd" "LED_0805 0.8 Red" 11027.56,4299.21 r0 top (schematic designator D10)
D10 "Red 0805 2.0V 20mA 104mCd" "LED_0805 0.8 Red" 11618.11,4299.21 r0 top (schematic designator D11)
D11 "Green" "T-1 3/4" 12204.72,5964.57 r270 top (schematic designator D17)
D12 "MBRA340T3G" SMA 9547.24,6732.28 r0 top (schematic designator D16)
D13 "MBRA340T3G" SMA 10781.5,6801.18 r270 top (schematic designator D12)
D14 "Green" "T-1 3/4" 12204.72,7440.94 r270 top
D15 "MBRA340T3G" SMA 9547.24,7047.24 r0 top (schematic designator D1)
D16 "MMSZ5242BT1G" SOD-123 11964.57,7307.09 r180 top (schematic designator D13)
D17 "Green" "T-1 3/4" 12204.72,8295.28 r270 top (schematic designator D15)
D18 "Red 0805 2.0V 20mA 104mCd" "LED_0805 0.8 Red" 5531.5,9488.19 r180 top (schematic designator D5)
D19 "Red 0805 2.0V 20mA 104mCd" "LED_0805 0.8 Red" 6318.9,9488.19 r180 top (schematic designator D4)
D20 "Red 0805 2.0V 20mA 104mCd" "LED_0805 0.8 Red" 7106.3,9488.19 r180 top (schematic designator D3)
D21 "Red 0805 2.0V 20mA 104mCd" "LED_0805 0.8 Red" 7893.7,9488.19 r180 top (schematic designator D2)
D22 "Red 0805 2.0V 20mA 104mCd" "LED_0805 0.8 Red" 8669.29,9480.32 r180 top (schematic designator D11)
D23 "Red 0805 2.0V 20mA 104mCd" "LED_0805 0.8 Red" 9259.84,9480.32 r180 top (schematic designator D10)
D24 "Red 0805 2.0V 20mA 104mCd" "LED_0805 0.8 Red" 9850.39,9480.31 r180 top (schematic designator D9)
D25 "Red 0805 2.0V 20mA 104mCd" "LED_0805 0.8 Red" 10440.94,9480.32 r180 top (schematic designator D8)
D26 "Red 0805 2.0V 20mA 104mCd" "LED_0805 0.8 Red" 11031.5,9480.31 r180 top (schematic designator D7)
D27 "Red 0805 2.0V 20mA 104mCd" "LED_0805 0.8 Red" 11625.98,9480.32 r180 top (schematic designator D6)
D28 "MMSZ5242BT1G" SOD-123 8464.57,6377.95 r0 top (schematic designator D18)
D30 "TVS Uni 26V 1500W" SMC 11996.06,6570.87 r270 top (schematic designator D20)
J1 "745-851" "WAGO 745-85X" 5807.09,5118.11 r180 top (schematic designator J4)
J2 "745-851" "WAGO 745-500" 5137.8,5118.11 r180 top (schematic designator J3)
J3 "745-85X Red" "WAGO 745-85X RED" 6200.79,5118.11 r180 top (schematic designator J5)
J4 "745-851" "WAGO 745-85X" 6594.49,5118.11 r180 top (schematic designator J6)
J5 "745-85X Red" "WAGO 745-85X RED" 6988.19,5118.11 r180 top (schematic designator J7)
J6 "745-851" "WAGO 745-85X" 7381.89,5118.11 r180 top (schematic designator J8)
J7 "745-85X Red" "WAGO 745-85X RED" 7775.59,5118.11 r180 top (schematic designator J9)
J8 "745-851" "WAGO 745-85X" 8169.29,5118.11 r180 top (schematic designator J10)
J9 "745-85X Red" "WAGO 745-85X RED" 8562.99,5118.11 r180 top (schematic designator J11)
J10 "745-300" "WAGO 745-300" 8503.94,5039.37 r180 top (schematic designator J12)
J11 "745-831" "WAGO 745-83X" 8799.21,5039.37 r180 top (schematic designator J13)
J12 "745-83X Red" "WAGO 745-83X Red" 9094.49,5039.37 r180 top (schematic designator J14)
J13 "745-831" "WAGO 745-83X" 9389.76,5039.37 r180 top (schematic designator J15)
J14 "745-83X Red" "WAGO 745-83X Red" 9685.04,5039.37 r180 top (schematic designator J16)
J15 "745-831" "WAGO 745-83X" 9980.32,5039.37 r180 top (schematic designator J17)
J16 "745-83X Red" "WAGO 745-83X Red" 10275.59,5039.37 r180 top (schematic designator J18)
J17 "745-831" "WAGO 745-83X" 10570.87,5039.37 r180 top (schematic designator J19)
J18 "745-83X Red" "WAGO 745-83X Red" 10866.14,5039.37 r180 top (schematic designator J20)
J19 "745-831" "WAGO 745-83X" 11161.42,5039.37 r180 top (schematic designator J21)
J20 "745-83X Red" "WAGO 745-83X Red" 11456.69,5039.37 r180 top (schematic designator J22)
J21 "745-831" "WAGO 745-83X" 11751.97,5039.37 r180 top (schematic designator J23)
J22 "745-83X Red" "WAGO 745-83X Red" 12047.24,5039.37 r180 top (schematic designator J24)
J23 "M6 Shank, Pressfit" "Wurth 7461098" 4527.56,5511.81 r0 top (schematic designator J1)
J24 "3.5mm Mini Header" "WAGO 734-132" 12283.46,5496.06 r90 top (schematic designator J27)
J25 "Sauro CTM040V8" "SAURO CTM040V8" 12293.31,6751.97 r90 top
J26 "3.5mm Mini Header" "WAGO 739-302" 12246.06,7818.9 r90 top
J27 "M6 Shank, Pressfit" "Wurth 7461098" 4527.56,8267.72 r0 top (schematic designator J2)
J28 "745-85X Red" "WAGO 745-85X RED" 4862.2,8661.42 r0 top (schematic designator J11)
J29 "745-851" "WAGO 745-85X" 5255.91,8661.42 r0 top (schematic designator J10)
J30 "745-85X Red" "WAGO 745-85X RED" 5649.61,8661.42 r0 top (schematic designator J9)
J31 "745-851" "WAGO 745-85X" 6043.31,8661.42 r0 top (schematic designator J8)
J32 "745-85X Red" "WAGO 745-85X RED" 6437.01,8661.42 r0 top (schematic designator J7)
J33 "745-851" "WAGO 745-85X" 6830.71,8661.42 r0 top (schematic designator J6)
J34 "745-85X Red" "WAGO 745-85X RED" 7224.41,8661.42 r0 top (schematic designator J5)
J35 "745-851" "WAGO 745-85X" 7618.11,8661.42 r0 top (schematic designator J4)
J36 "745-851" "WAGO 745-500" 8287.4,8661.42 r0 top (schematic designator J3)
J37 "745-83X Red" "WAGO 745-83X Red" 8240.16,8740.16 r0 top (schematic designator J24)
J38 "745-831" "WAGO 745-83X" 8535.43,8740.16 r0 top (schematic designator J23)
J39 "745-83X Red" "WAGO 745-83X Red" 8830.71,8740.16 r0 top (schematic designator J22)
J40 "745-831" "WAGO 745-83X" 9125.98,8740.16 r0 top (schematic designator J21)
J41 "745-83X Red" "WAGO 745-83X Red" 9421.26,8740.16 r0 top (schematic designator J20)
J42 "745-831" "WAGO 745-83X" 9716.54,8740.16 r0 top (schematic designator J19)
J43 "745-83X Red" "WAGO 745-83X Red" 10011.81,8740.16 r0 top (schematic designator J18)
J44 "745-831" "WAGO 745-83X" 10307.09,8740.16 r0 top (schematic designator J17)
J45 "745-83X Red" "WAGO 745-83X Red" 10602.36,8740.16 r0 top (schematic designator J16)
J46 "745-831" "WAGO 745-83X" 10897.64,8740.16 r0 top (schematic designator J15)
J47 "745-83X Red" "WAGO 745-83X Red" 11192.91,8740.16 r0 top (schematic designator J14)
J48 "745-831" "WAGO 745-83X" 11488.19,8740.16 r0 top (schematic designator J13)
J49 "745-300" "WAGO 745-300" 11783.46,8740.16 r0 top (schematic designator J12)
L1 "4.7 µH 6 A" "WURTH WE-HC 744314X" 9232.28,6456.69 r270 top (schematic designator L3)
L2 "18 µH 3.35A ±20% SMD" "COILCRAFT MSS1038" 11072.83,6852.36 r180 top
L3 "4.7 µH 6 A" "WURTH WE-HC 744314X" 9232.28,7322.83 r270 top (schematic designator L1)
L4 "0 ohm 1210" R1210_C 10421.26,7035.43 r0 top
L5 "0 ohm 1210" R1210_C 10539.37,6779.53 r0 top
Q1 "FDV302P" "SOT-23 FET" 5351.28,5728.35 r245 top (schematic designator Q2)
Q2 "FDV302P" "SOT-23 FET" 6138.69,5728.35 r245 top (schematic designator Q3)
Q3 "FDV302P" "SOT-23 FET" 6926.09,5728.35 r245 top (schematic designator Q4)
Q4 "FDV302P" "SOT-23 FET" 7713.49,5728.35 r245 top (schematic designator Q5)
Q5 "FDV302P" "SOT-23 FET" 8543.31,5811.02 r180 top (schematic designator Q6)
Q6 "FDV302P" "SOT-23 FET" 9133.86,5811.02 r180 top (schematic designator Q7)
Q7 "FDV302P" "SOT-23 FET" 9724.41,5811.02 r180 top (schematic designator Q8)
Q8 "FDV302P" "SOT-23 FET" 10314.96,5811.02 r180 top (schematic designator Q9)
Q9 "FDV302P" "SOT-23 FET" 10905.51,5811.02 r180 top (schematic designator Q10)
Q10 "FDV302P" "SOT-23 FET" 11496.06,5811.02 r180 top (schematic designator Q11)
Q11 "IRF8721PbF" "SO-8_M FET" 9566.93,6535.43 r180 top (schematic designator Q12)
Q12 "FQB33N10TM" TO-263AB/D2PAK 8582.68,6614.17 r0 top (schematic designator Q13)
Q13 "FDS8447" "SO-8_M FET" 9566.93,7322.83 r180 top (schematic designator Q1)
Q14 "FDV302P" "SOT-23 FET" 8791.34,7968.5 r0 top (schematic designator Q11)
Q15 "FDV302P" "SOT-23 FET" 9381.89,7968.5 r0 top (schematic designator Q10)
Q16 "FDV302P" "SOT-23 FET" 9972.44,7968.5 r0 top (schematic designator Q9)
Q17 "FDV302P" "SOT-23 FET" 10562.99,7968.5 r0 top (schematic designator Q8)
Q18 "FDV302P" "SOT-23 FET" 11153.54,7968.5 r0 top (schematic designator Q7)
Q19 "FDV302P" "SOT-23 FET" 11744.09,7968.5 r0 top (schematic designator Q6)
Q20 "FDV302P" "SOT-23 FET" 5711.71,8051.18 r65 top (schematic designator Q5)
Q21 "FDV302P" "SOT-23 FET" 6499.11,8051.18 r65 top (schematic designator Q4)
Q22 "FDV302P" "SOT-23 FET" 7286.51,8051.18 r65 top (schematic designator Q3)
Q23 "FDV302P" "SOT-23 FET" 8073.91,8051.18 r65 top (schematic designator Q2)
R1 "240 ohm 1206 5%" R1206_C 5187.01,4291.34 r0 top (schematic designator R8)
R2 "270 ohm 1206 5%" R1206_C 5358.27,4291.34 r0 top (schematic designator R12)
R3 "240 ohm 1206 5%" R1206_C 5978.35,4291.34 r0 top (schematic designator R9)
R4 "270 ohm 1206 5%" R1206_C 6141.73,4291.34 r0 top (schematic designator R13)
R5 "240 ohm 1206 5%" R1206_C 6765.75,4291.34 r0 top (schematic designator R10)
R6 "270 ohm 1206 5%" R1206_C 6933.07,4291.34 r0 top (schematic designator R14)
R7 "240 ohm 1206 5%" R1206_C 7549.21,4291.34 r0 top (schematic designator R11)
R8 "270 ohm 1206 5%" R1206_C 7716.54,4291.34 r0 top (schematic designator R15)
R9 "240 ohm 1206 5%" R1206_C 8488.19,4299.21 r0 top (schematic designator R16)
R10 "270 ohm 1206 5%" R1206_C 8836.61,4295.28 r0 top (schematic designator R22)
R11 "240 ohm 1206 5%" R1206_C 9082.68,4299.21 r0 top (schematic designator R17)
R12 "270 ohm 1206 5%" R1206_C 9431.1,4295.28 r0 top (schematic designator R23)
R13 "240 ohm 1206 5%" R1206_C 9673.23,4299.21 r0 top (schematic designator R18)
R14 "270 ohm 1206 5%" R1206_C 10021.65,4295.28 r0 top (schematic designator R24)
R15 "240 ohm 1206 5%" R1206_C 10263.78,4299.21 r0 top (schematic designator R19)
R16 "270 ohm 1206 5%" R1206_C 10610.24,4299.21 r0 top (schematic designator R25)
R17 "240 ohm 1206 5%" R1206_C 10856.3,4299.21 r0 top (schematic designator R20)
R18 "270 ohm 1206 5%" R1206_C 11200.79,4299.21 r0 top (schematic designator R26)
R19 "240 ohm 1206 5%" R1206_C 11446.85,4299.21 r0 top (schematic designator R21)
R20 "270 ohm 1206 5%" R1206_C 11791.34,4299.21 r0 top (schematic designator R27)
R21 "510 ohm 1206 1%" R1206_C 12017.72,5974.41 r270 top (schematic designator R51)
R22 "100k ohm 0603 1%" R0603_C 5364.17,5885.83 r0 top (schematic designator R32)
R23 "100k ohm 0603 1%" R0603_C 6151.57,5885.83 r0 top (schematic designator R33)
R24 "100k ohm 0603 1%" R0603_C 6938.98,5885.83 r0 top (schematic designator R34)
R25 "100k ohm 0603 1%" R0603_C 7726.38,5885.83 r0 top (schematic designator R35)
R26 "100k ohm 0603 1%" R0603_C 8968.5,5807.09 r270 top (schematic designator R36)
R27 "100k ohm 0603 1%" R0603_C 9559.06,5807.09 r270 top (schematic designator R37)
R28 "100k ohm 0603 1%" R0603_C 10149.61,5807.09 r270 top (schematic designator R38)
R29 "100k ohm 0603 1%" R0603_C 10740.16,5807.09 r270 top (schematic designator R39)
R30 "100k ohm 0603 1%" R0603_C 11330.71,5807.09 r270 top (schematic designator R40)
R31 "100k ohm 0603 1%" R0603_C 11921.26,5807.09 r270 top (schematic designator R41)
R32 "15 milliohm RL3720 2% 1W" "RL3720 - SUSUMU" 9793.31,6503.94 r180 top (schematic designator R48)
R33 "604 ohm 0603 1%" R0603_C 9793.31,6336.61 r180 top (schematic designator R45)
R34 "20 ohm 0603 1%" R0603_C 10108.27,6466.54 r270 top (schematic designator R42)
R35 "510 ohm 1206 1%" R1206_C 11751.97,7283.46 r0 top (schematic designator R30)
R36 "24k ohm 0603 1%" R0603_C 9970.47,6540.35 r90 top (schematic designator R43)
R37 "1.0k ohm 0603 1%" R0603_C 10285.43,6555.12 r180 top (schematic designator R44)
R38 "0 ohm 0603" R0603_C 9793.31,6624.02 r180 top (schematic designator R50)
R39 "1.0k ohm 0603 1%" R0603_C 10255.75,6467.17 r90 top (schematic designator R47)
R40 "8.45k ohm 0603 1%" R0603_C 10314.8,6467.17 r270 top (schematic designator R46)
R41 "18k ohm 0603 1%" R0603_C 10255.91,7269.69 r270 top (schematic designator R5)
R42 "1.0k ohm 0603 1%" R0603_C 10314.96,7269.69 r90 top (schematic designator R6)
R43 "10k ohm 0603 1%" R0603_C 10728.35,6978.35 r0 top (schematic designator R28)
R44 "604 ohm 0603 1%" R0603_C 9793.31,7124.02 r180 top (schematic designator R4)
R45 "3.16k ohm 0603 1%" R0603_C 10728.35,7037.4 r180 top (schematic designator R29)
R46 "15 milliohm RL3720 2% 1W" "RL3720 - SUSUMU" 9793.31,7291.34 r180 top (schematic designator R7)
R47 "20 ohm 0603 1%" R0603_C 10108.27,7253.94 r90 top (schematic designator R1)
R48 "24k ohm 0603 1%" R0603_C 9970.47,7327.76 r90 top (schematic designator R2)
R49 "1.0k ohm 0603 1%" R0603_C 10285.43,7342.52 r180 top (schematic designator R3)
R50 "0 ohm 0603" R0603_C 9793.31,7411.42 r180 top (schematic designator R49)
R51 "100k ohm 0603 1%" R0603_C 5698.82,7893.7 r180 top (schematic designator R35)
R52 "100k ohm 0603 1%" R0603_C 6486.22,7893.7 r180 top (schematic designator R34)
R53 "100k ohm 0603 1%" R0603_C 7273.62,7893.7 r180 top (schematic designator R33)
R54 "100k ohm 0603 1%" R0603_C 8061.02,7893.7 r180 top (schematic designator R32)
R55 "100k ohm 0603 1%" R0603_C 8366.14,7972.44 r90 top (schematic designator R41)
R56 "100k ohm 0603 1%" R0603_C 8956.69,7972.44 r90 top (schematic designator R40)
R57 "100k ohm 0603 1%" R0603_C 9547.24,7972.44 r90 top (schematic designator R39)
R58 "100k ohm 0603 1%" R0603_C 10137.8,7972.44 r90 top (schematic designator R38)
R59 "100k ohm 0603 1%" R0603_C 10728.35,7976.38 r90 top (schematic designator R37)
R60 "100k ohm 0603 1%" R0603_C 11318.9,7972.44 r90 top (schematic designator R36)
R61 "130 ohm 0603 1%" R0603_C 12204.72,8515.75 r270 top (schematic designator R31)
R62 "270 ohm 1206 5%" R1206_C 5708.66,9488.19 r180 top (schematic designator R15)
R63 "240 ohm 1206 5%" R1206_C 5875.98,9488.19 r180 top (schematic designator R11)
R64 "270 ohm 1206 5%" R1206_C 6492.13,9488.19 r180 top (schematic designator R14)
R65 "240 ohm 1206 5%" R1206_C 6659.45,9488.19 r180 top (schematic designator R10)
R66 "270 ohm 1206 5%" R1206_C 7283.46,9488.19 r180 top (schematic designator R13)
R67 "240 ohm 1206 5%" R1206_C 7446.85,9488.19 r180 top (schematic designator R9)
R68 "270 ohm 1206 5%" R1206_C 8066.93,9488.19 r180 top (schematic designator R12)
R69 "240 ohm 1206 5%" R1206_C 8238.19,9488.19 r180 top (schematic designator R8)
R70 "270 ohm 1206 5%" R1206_C 8496.06,9480.31 r180 top (schematic designator R27)
R71 "240 ohm 1206 5%" R1206_C 8840.55,9480.31 r180 top (schematic designator R21)
R72 "270 ohm 1206 5%" R1206_C 9086.61,9480.31 r180 top (schematic designator R26)
R73 "240 ohm 1206 5%" R1206_C 9431.1,9480.31 r180 top (schematic designator R20)
R74 "270 ohm 1206 5%" R1206_C 9677.17,9480.32 r180 top (schematic designator R25)
R75 "240 ohm 1206 5%" R1206_C 10023.62,9480.31 r180 top (schematic designator R19)
R76 "270 ohm 1206 5%" R1206_C 10265.75,9484.25 r180 top (schematic designator R24)
R77 "240 ohm 1206 5%" R1206_C 10614.17,9480.32 r180 top (schematic designator R18)
R78 "270 ohm 1206 5%" R1206_C 10856.3,9484.25 r180 top (schematic designator R23)
R79 "240 ohm 1206 5%" R1206_C 11204.72,9480.31 r180 top (schematic designator R17)
R80 "270 ohm 1206 5%" R1206_C 11450.79,9484.25 r180 top (schematic designator R22)
R81 "240 ohm 1206 5%" R1206_C 11799.21,9480.32 r180 top (schematic designator R16)
R82 "200k ohm 0603 1%" R0603_C 5385.83,5970.47 r90 top (schematic designator R52)
R83 "200k ohm 0603 1%" R0603_C 6173.23,5970.47 r90 top (schematic designator R53)
R84 "200k ohm 0603 1%" R0603_C 6960.63,5970.47 r90 top (schematic designator R54)
R85 "200k ohm 0603 1%" R0603_C 7748.03,5970.47 r90 top (schematic designator R55)
R86 "200k ohm 0603 1%" R0603_C 8039.37,7809.06 r270 top (schematic designator R52)
R87 "200k ohm 0603 1%" R0603_C 7251.97,7809.06 r270 top (schematic designator R53)
R88 "200k ohm 0603 1%" R0603_C 6464.57,7809.06 r270 top (schematic designator R54)
R89 "200k ohm 0603 1%" R0603_C 5677.17,7809.06 r270 top (schematic designator R55)
R90 "200k ohm 0603 1%" R0603_C 11251.97,7972.44 r90 top (schematic designator R56)
R91 "200k ohm 0603 1%" R0603_C 10661.42,7976.38 r90 top (schematic designator R57)
R92 "200k ohm 0603 1%" R0603_C 10070.87,7972.44 r90 top (schematic designator R58)
R93 "200k ohm 0603 1%" R0603_C 9480.32,7972.44 r90 top (schematic designator R59)
R94 "200k ohm 0603 1%" R0603_C 8889.76,7972.44 r90 top (schematic designator R60)
R95 "200k ohm 0603 1%" R0603_C 8299.21,7972.44 r90 top (schematic designator R61)
R96 "200k ohm 0603 1%" R0603_C 9035.43,5807.09 r270 top (schematic designator R56)
R97 "200k ohm 0603 1%" R0603_C 9625.98,5807.09 r270 top (schematic designator R57)
R98 "200k ohm 0603 1%" R0603_C 10216.54,5807.09 r270 top (schematic designator R58)
R99 "200k ohm 0603 1%" R0603_C 10807.09,5807.09 r270 top (schematic designator R59)
R100 "200k ohm 0603 1%" R0603_C 11397.64,5807.09 r270 top (schematic designator R60)
R101 "200k ohm 0603 1%" R0603_C 11988.19,5807.09 r270 top (schematic designator R61)
R102 "100k ohm 0603 1%" R0603_C 8500,6299.21 r0 top (schematic designator R62)
U1 "Buck Converter" TPS543X 10962.83,6504.13 r0 top (schematic designator U2)
U2 "LM3478" MUA08A 10118.11,6586.61 r90 top (schematic designator U3)
U3 "LM3478" MUA08A 10118.11,7374.02 r90 top (schematic designator U1)

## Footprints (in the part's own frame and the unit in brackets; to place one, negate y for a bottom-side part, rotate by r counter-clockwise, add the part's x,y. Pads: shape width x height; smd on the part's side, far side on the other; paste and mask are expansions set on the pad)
2920L [mm] "POLYFUSE® Resettable PTCs  Surface Mount > 2920L Series"
  rect 2x5.3 smd: 1(-3.3,0) 2(3.3,0)
  silkscreen extent -2,-2.7 2,2.7
C0603_C [mm]
  rect 0.6x0.9 smd: 1(-0.75,0) 2(0.75,0)
  silkscreen extent -1,-0.53 1,0.53
C0805_C [mm]
  rect 0.9x1.3 smd: 1(-0.95,0) 2(0.95,0)
  silkscreen extent -1.43,-0.76 1.43,0.76
C1210_C [mil]
  rect 65x110 smd: 1(-55,0) 2(55,0)
  silkscreen extent -95,-60 95,60
"COILCRAFT MSS1038" [mm] "SMT Power Inductors"
  rect 3.56x1.78 smd: 1(0,4.7) 2(0,-4.7)
  silkscreen extent -5.2,-5.3 5.2,5.3
"FUSE2410 - BEL" [mm] "bel SSQ Square Ceramic Surface Mount Quick Acting Fuse"
  rect 2x3.18 smd: 1(-2.5,0) 2(2.5,0)
  silkscreen extent -1.3,-1.4 1.3,1.4
"KEYSTONE 3555-2" [mm]
  round 4.5 / inner round 7 / far side round 7 hole 3.9: 1(-14.75,0) 1(-6.35,0) 2(6.35,0) 2(14.75,0)
"KEYSTONE 3557-2" [mm]
  round 2.4 / inner round 3.4 / far side oval 3.4x3.5 hole 1.7: 1(-6.75,-1.7) 1(-6.75,1.7) 2(6.75,-1.7) 2(6.75,1.7)
  silkscreen extent -10.1,-3.6 10.1,3.6
"LED_0805 0.8 Red" [mm] "0.8mm Red 0805 Led"
  rect 1.2x1.2 smd: A(-1.05,0) K(1.05,0)
  silkscreen extent 0,-0.82 0.22,0.83
MUA08A [mm] "Shrink Small Outline; 8 Leads; Body Width 3 mm; Pitch 0.65 mm"
  rect 0.4x1.55 smd: 1(-0.975,-2.075) 2(-0.325,-2.075) 3(0.325,-2.075) 4(0.975,-2.075) 5(0.975,2.075) 6(0.325,2.075) 7(-0.325,2.075) 8(-0.975,2.075)
  silkscreen extent -1.85,-2.2 1.55,0.9
PTC-MF-SM-Large [mm]
  rect 2.3x4.6 smd: 1(-4.2,0) 2(4.2,0)
  silkscreen extent -3.9,-3.3 3.9,3.3
PTC-MF-SM-Small [mm]
  rect 2.3x3.1 smd: 1(-3.7,0) 2(3.7,0)
  silkscreen extent -3.9,-2.6 3.9,2.6
R0603_C [mm]
  rect 0.6x0.9 smd: 1(-0.75,0) 2(0.75,0)
  silkscreen extent -1,-0.53 1,0.53
R1206_C [mm]
  rect 0.9x1.6 smd: 1(-1.45,0) 2(1.45,0)
  silkscreen extent -1.02,-0.89 1.02,0.89
R1210_C [mil]
  rect 65x110 smd: 1(-55,0) 2(55,0)
  silkscreen extent -20,-52 20,50
"RL3720 - SUSUMU" [mm] "Susumu Long-side electrode Resistors"
  rect 0.75x4.2 smd: 1(-0.975,0) 2(0.975,0)
  silkscreen extent -0.25,-0.76 0.25,0.76
"SAURO CTM040V8" [mm] "4 position vertical thru-hole connector with locking screw flanges, 3.5mm spacing"
  round 1.8 hole 1.2: 1(-5.25,0) 2(-1.75,0) 3(1.75,0) 4(5.25,0)
  silkscreen extent -12.15,-4 12.15,3
SMA [mm] "DO-214-AC/SMA; 2 C-Bend Leads; Body 5.6 x 2.9 mm, inc. leads (LxW)"
  rect 2x2 smd: A(-2,0) K(2,0)
  silkscreen extent -0.8,-1.8 3.2,1.8
SMC [mm] "DO-214-AB/SMC; 2 C-Bend Leads; Body 7.9 x 5.9 mm, inc. leads (LxW)"
  rect 2.4x3.3 smd: A(-3.475,0) K(3.475,0)
  silkscreen extent -0.8,-3.2 5.43,3.2
"SMT-CAN NIPPON F80" [mm] "Nippon ChemiCon SMT-CAN type Capacitor, Size code F80"
  rect 1.6x3.5 smd: +(0,2.7) -(0,-2.7)
  silkscreen extent -3.45,-3.7 3.45,4.1
"SMT-CAN Panasonic D8" [mm] "Panasonic SMT-CAN type Capacitor, Size code D8"
  rect 1.6x3.2 smd: +(0,2.4) -(0,-2.4)
  silkscreen extent -3.5,-3.9 3.5,4.2
"SO-8_M FET" [mm] "8-Pin Plastic Small Outline Integrated Circuit 1.27 mm Pitch, IPC Low Density"
  oval 2.5x0.7 smd: D(2.45,1.905) D(2.45,-0.635) D(2.45,0.635) D(2.45,-1.905) G(-2.45,-1.905) S(-2.45,1.905) S(-2.45,-0.635) S(-2.45,0.635)
  silkscreen extent -2.58,-2.5 0.8,2.93
SOD-123 [mm]
  rect 0.91x1.22 smd: A(1.638,0) K(-1.638,0)
  silkscreen extent -2.18,-0.9 1.42,0.9
"SOT-23 FET" [mm]
  rect 0.9x0.8 smd: D(1,0) G(-1,0.95) S(-1,-0.95)
  silkscreen extent 0.1,-1.5 0.7,1.5
"T-1 3/4" [mil]
  round 60 hole 35: A(-50,0)
  rect 60x60 hole 35: K(50,0)
  silkscreen extent -116,-116 98,116
TO-263AB/D2PAK [mm]
  rect 9.5x10 smd: D(0,10)
  rect 1.7x4.2 smd: G(-2.54,0) S(2.54,0)
  silkscreen extent -5.4,2.5 5.4,14.1
TPS543X [mil] "Thermally Enhanced SO8"
  rect 80x26 smd: 1(-110,75) 2(-110,25) 3(-110,-25) 4(-110,-75) 5(110,-75) 6(110,-25) 7(110,25) 8(110,75)
  rect 50x60 hole 12.99: PAD(-20,-25) PAD(-20,25) PAD(20,-25) PAD(20,25)
  rect 98x118 smd: PAD(0,0)
  silkscreen extent -107,-98 51,113
"WAGO 734-132" [mm] "3.5mm 10 A Protected Header"
  oct 2.8x2.8 hole 1.4: 1(0,0)
  round 2.8 hole 1.4: 2(3.5,0)
  silkscreen extent -2.8,-4.35 6.6,4.15
"WAGO 739-302" [mm] "3.5mm 6 A"
  oct 2.8x2.8 hole 1.1: 1(0,0)
  round 2.8 hole 1.1: 2(3.5,0)
  silkscreen extent -1.75,-5.7 6.75,7.7
"WAGO 745-83X" [mm] "1 Poles of the 745-83X"
  rect 3.048x3.048 / inner rect 3.6x3.6 / far side rect 3.6x3.6 hole 1.8: 1(7.5,12.5) 1(7.5,0)
  silkscreen extent 3.4,-8.6 10.9,17.8
"WAGO 745-83X Red" [mm] "1 Poles of the 745-83X"
  rect 3.048x3.048 / inner rect 3.6x3.6 / far side rect 3.6x3.6 hole 1.8: 1(7.5,12.5) 1(7.5,0)
  silkscreen extent 3.4,-8.6 10.9,17.8
"WAGO 745-85X" [mm] "1 Pole of 745-85X"
  rect 3.048x3.048 / inner rect 4.4x4.4 / far side rect 4.4x4.4 hole 2.2: 1(10,15) 1(10,0) 1(14,15) 1(14,0)
  silkscreen extent 7,-10 17,19.6
"WAGO 745-85X RED" [mm] "1 Pole of 745-85X"
  rect 3.048x3.048 / inner rect 4.4x4.4 / far side rect 4.4x4.4 hole 2.2: 1(10,15) 1(10,0) 1(14,15) 1(14,0)
  silkscreen extent 7,-10 17,19.6
"WAGO 745-300" [mil] "745-83X End Plate"
  silkscreen extent 134,-339 197,669
"WAGO 745-500" [mil] "745-85X End Plate"
  silkscreen extent 0,-394 0,748
"Wurth 7461098" [mil] "M6 Press Fit Shank"
  round 85 hole 57.09: PAD(-200,-200) PAD(-200,-100) PAD(-200,0) PAD(-200,100) PAD(-200,200) PAD(-100,-200) PAD(-100,-100) PAD(-100,0) PAD(-100,100) PAD(-100,200) PAD(0,-200) PAD(0,-100) PAD(0,0) PAD(0,100) PAD(0,200) PAD(100,-200) PAD(100,-100) PAD(100,0) PAD(100,100) PAD(100,200) PAD(200,-200) PAD(200,-100) PAD(200,0) PAD(200,100) PAD(200,200)
  silkscreen extent -354,-354 354,354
